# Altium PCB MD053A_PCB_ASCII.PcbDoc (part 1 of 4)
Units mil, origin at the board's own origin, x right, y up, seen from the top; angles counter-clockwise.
Board outline 3650 x 5180 mil, 4 copper layers (Top Layer, GND Layer, Power Layer, Bottom Layer), stack 58.4 mil thick; 251 components, 138 nets, 532 pads, 1017 vias.
Unrouted connection lines stored in the file: 42.
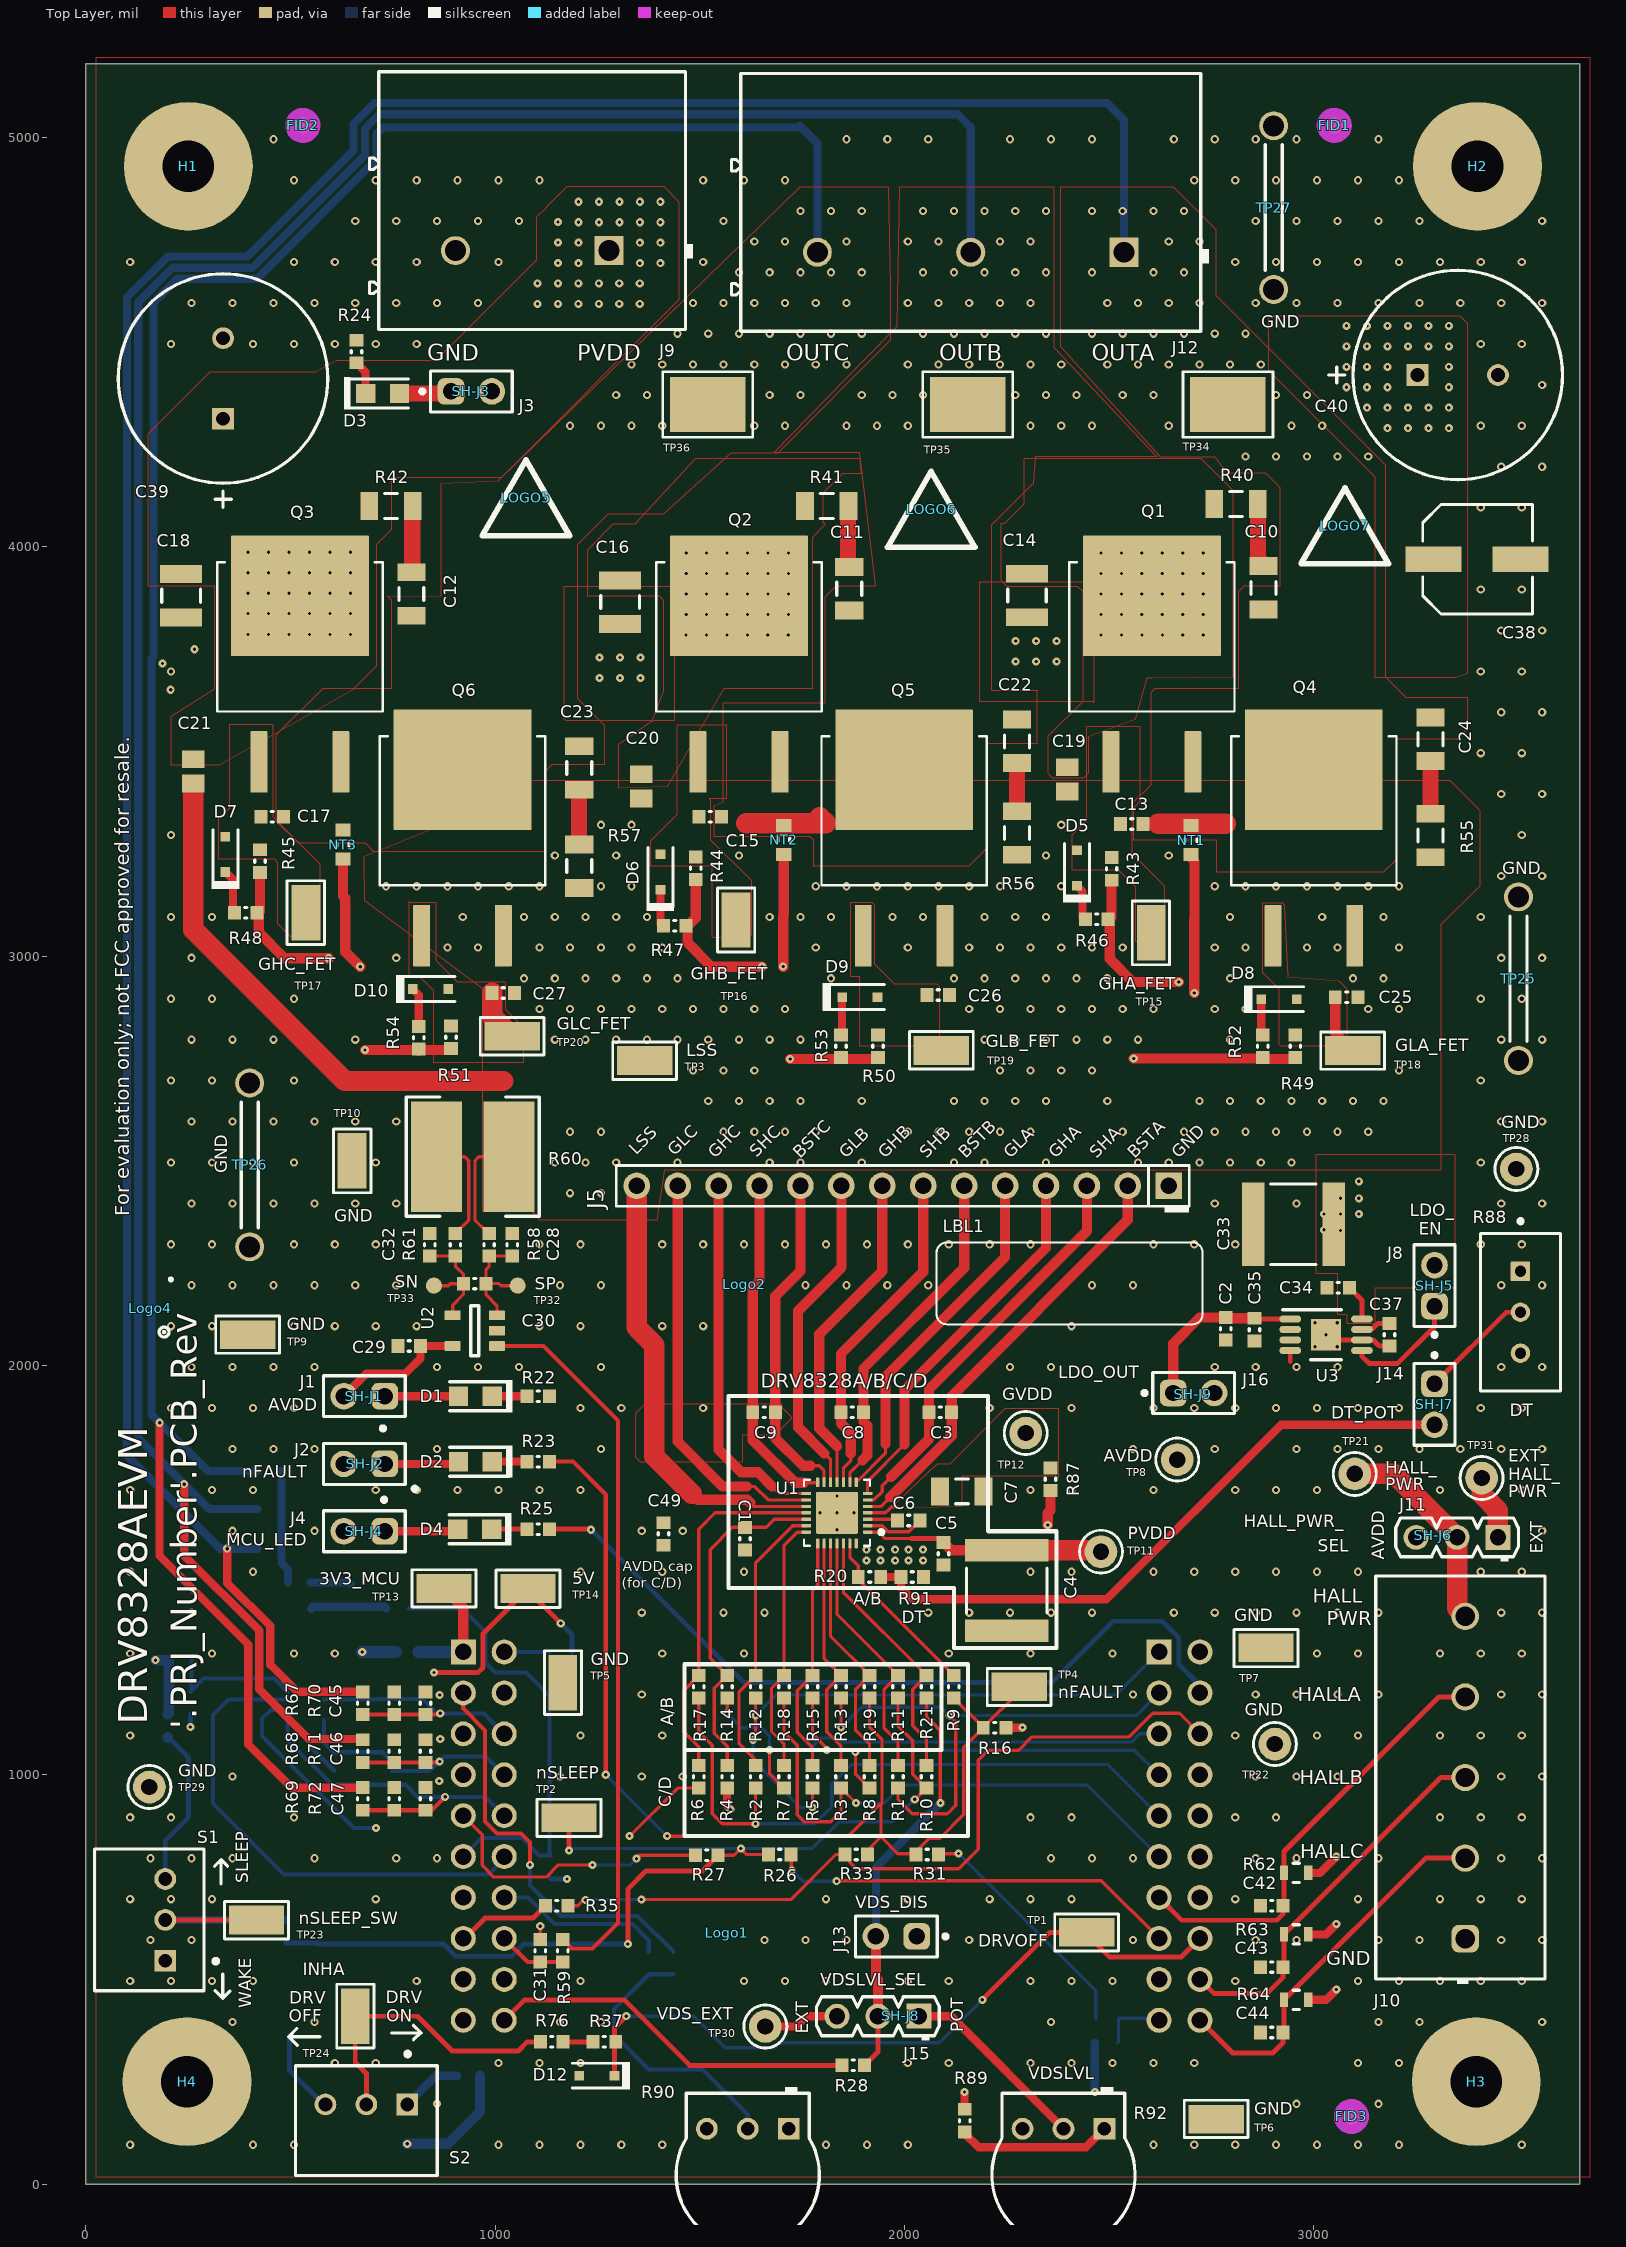
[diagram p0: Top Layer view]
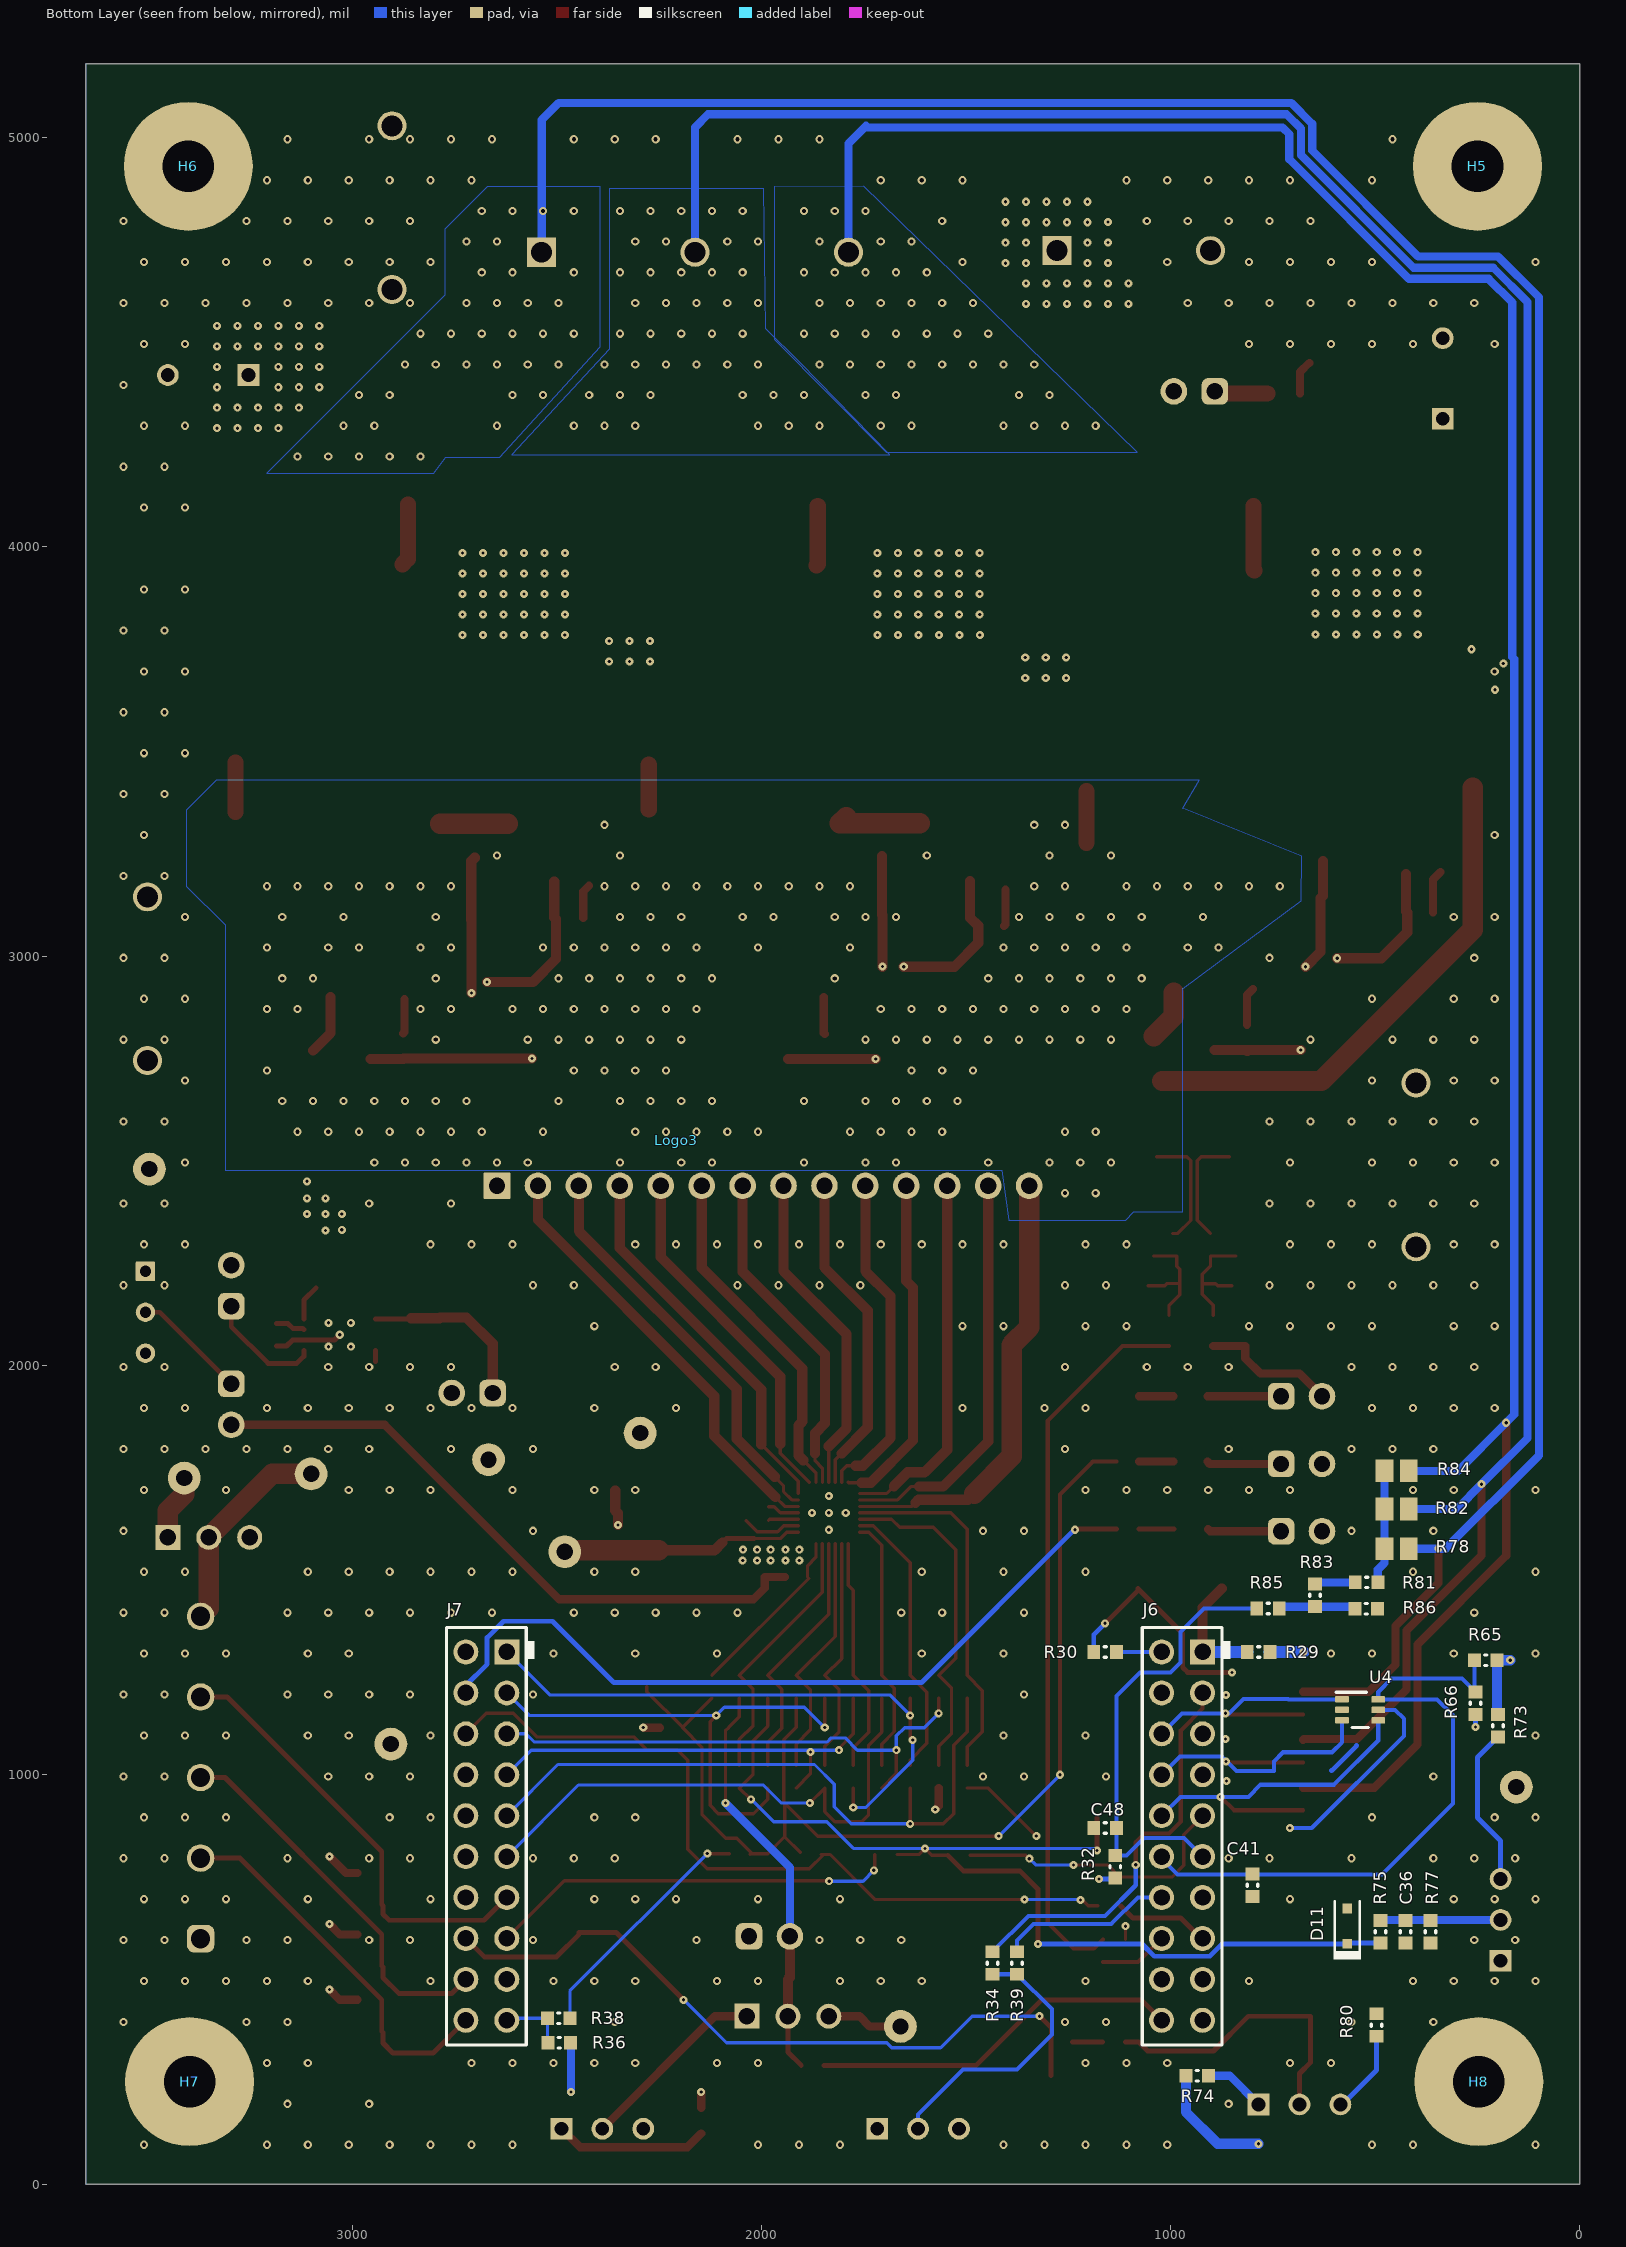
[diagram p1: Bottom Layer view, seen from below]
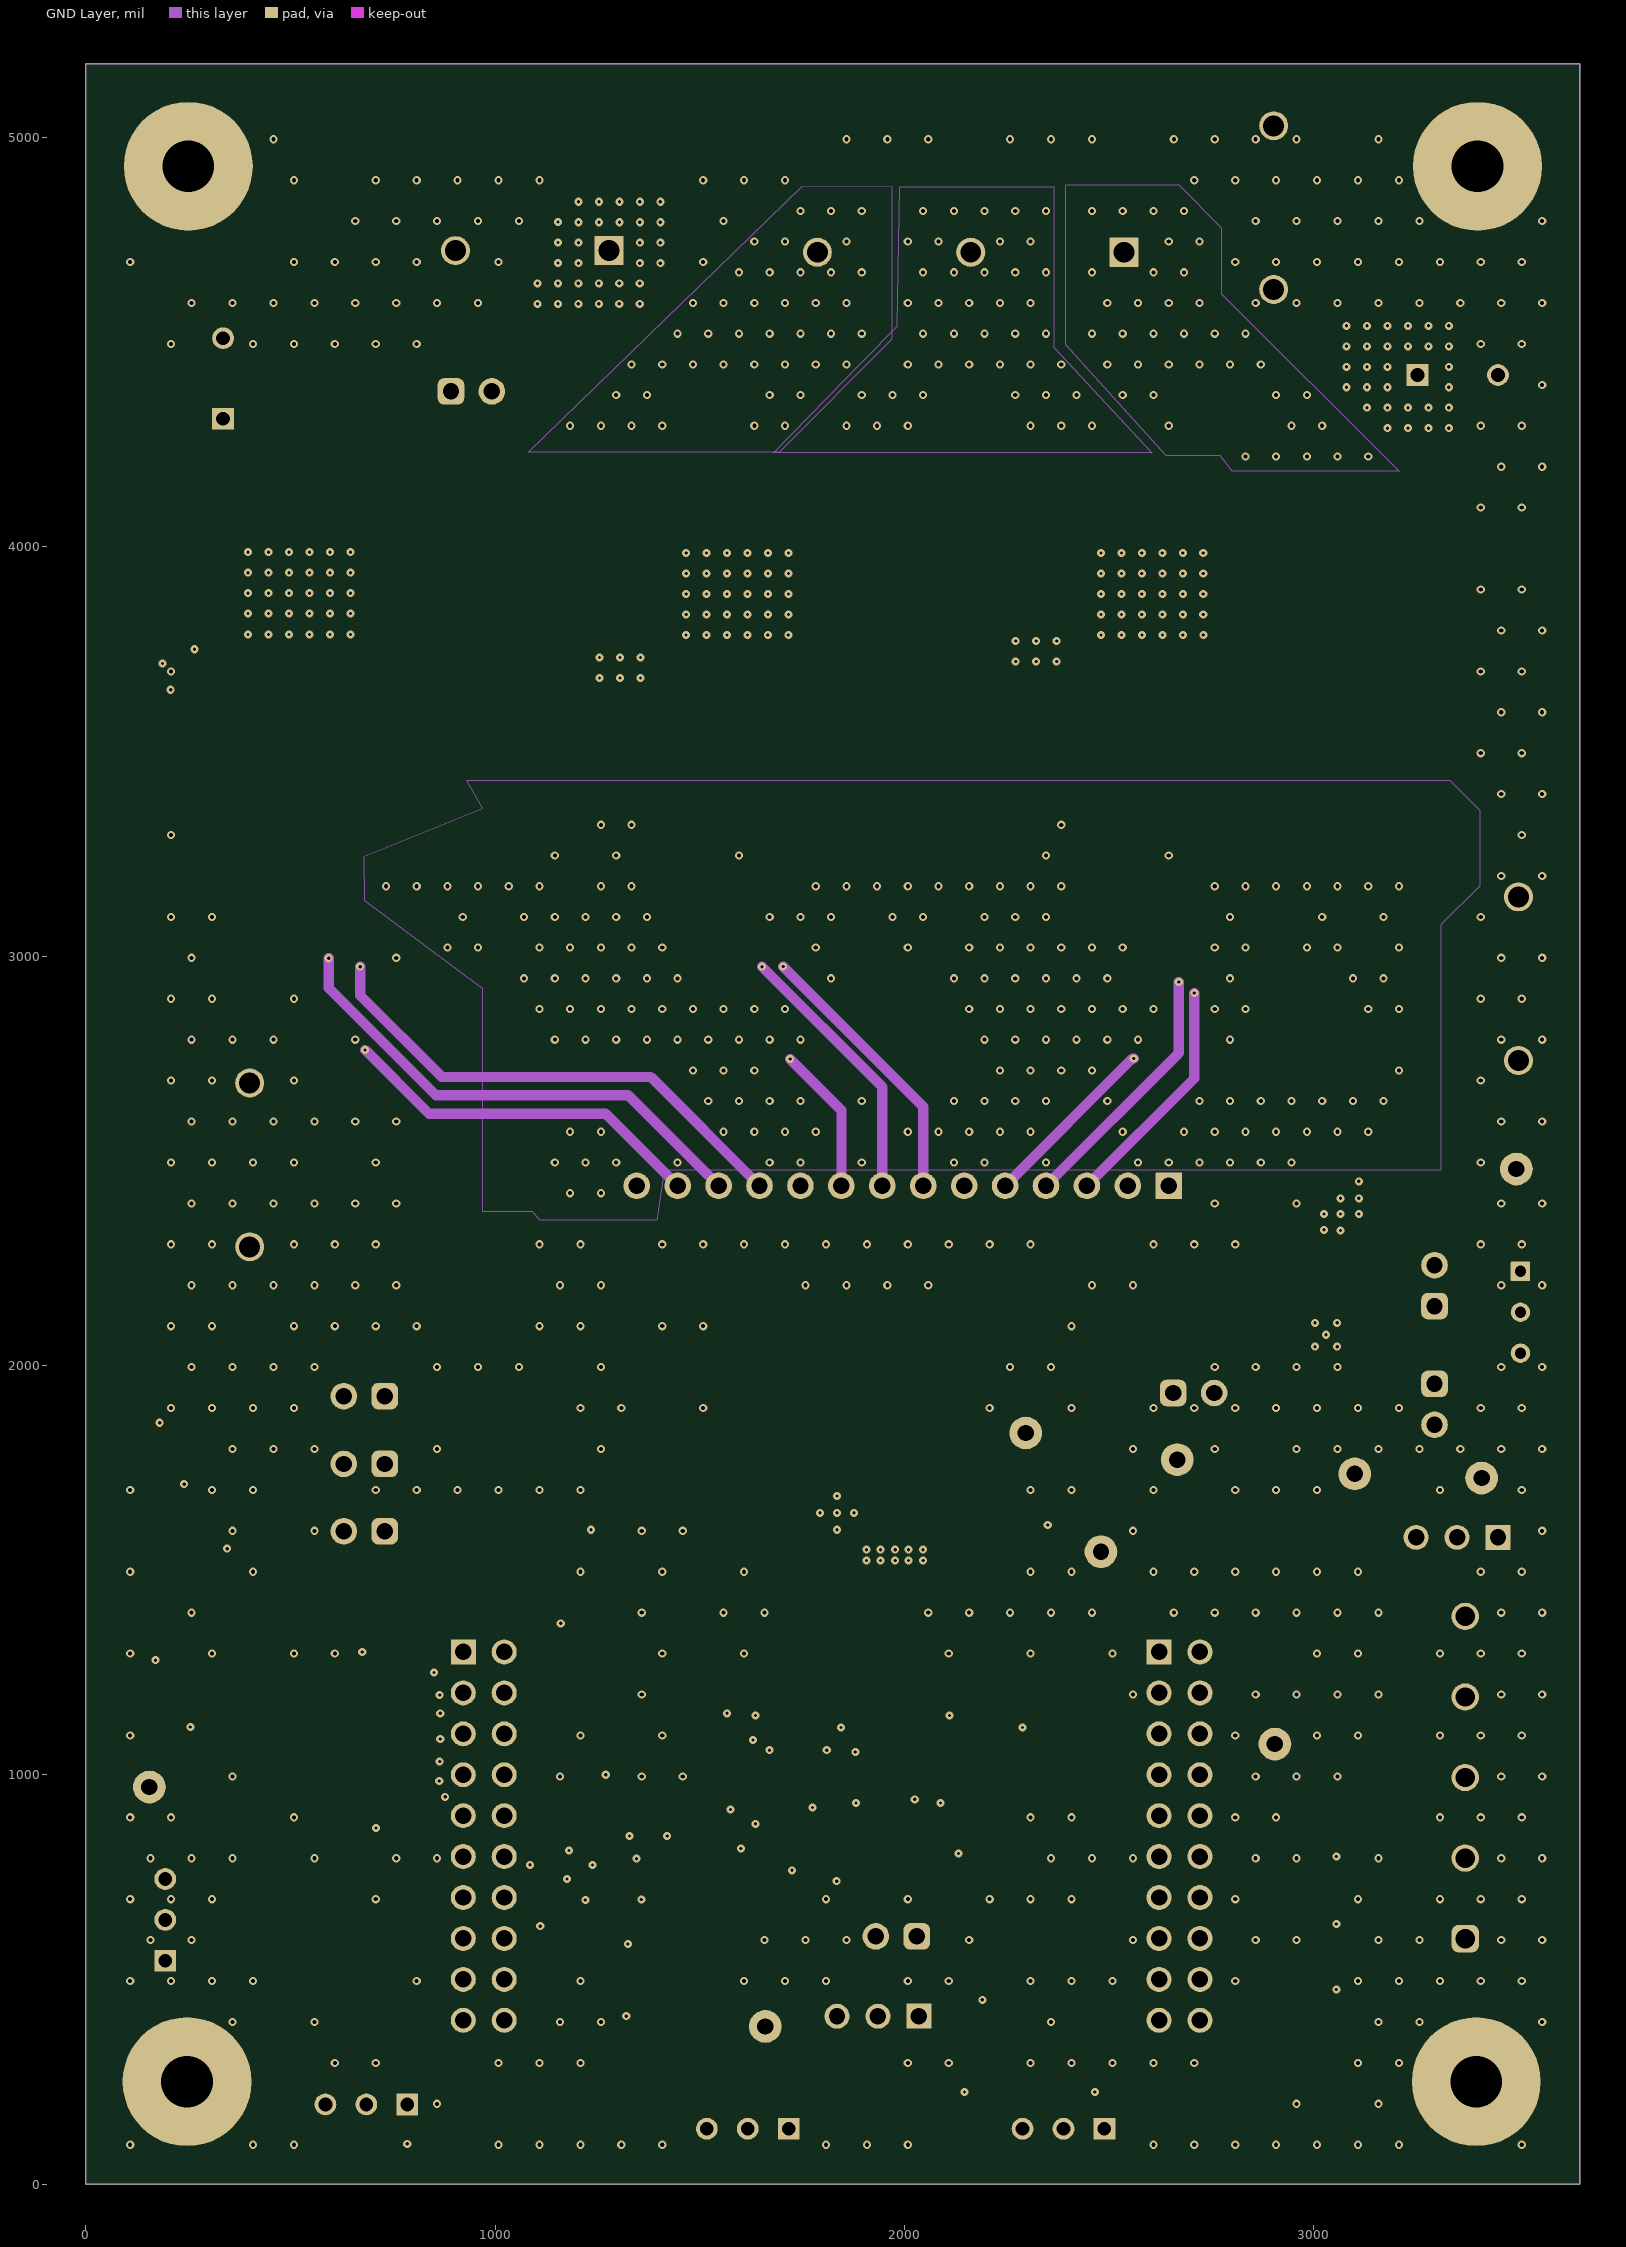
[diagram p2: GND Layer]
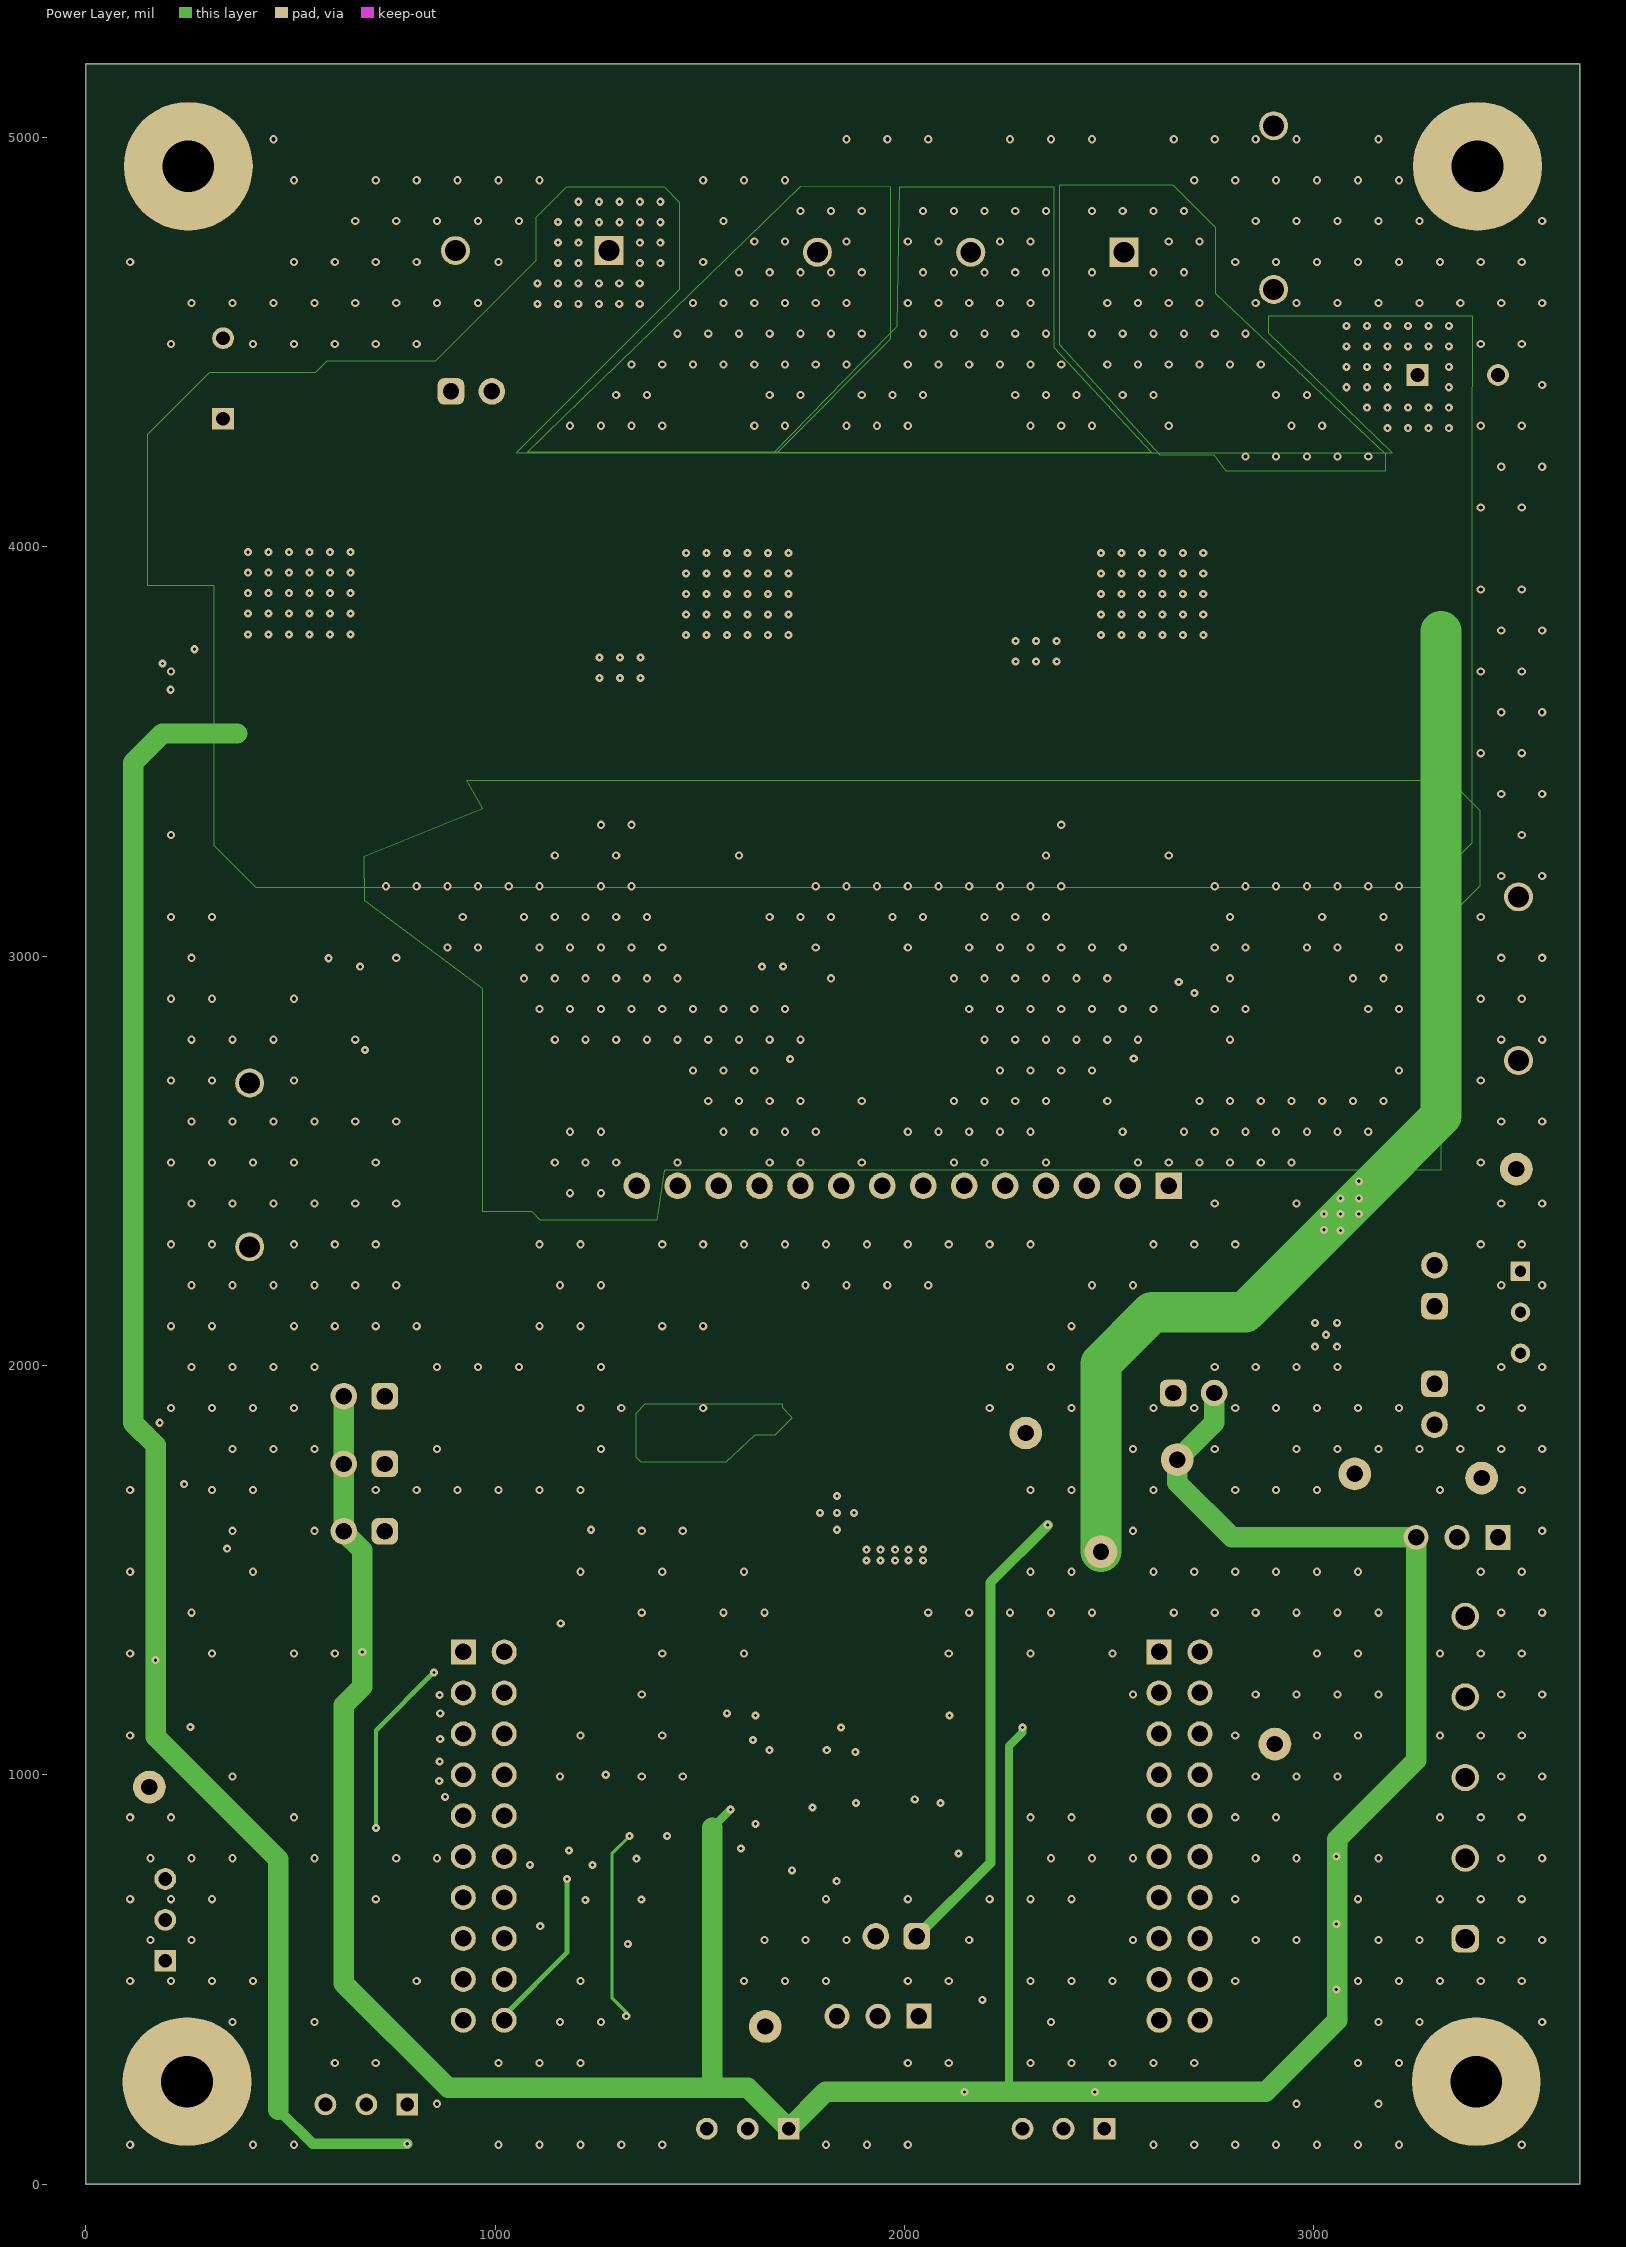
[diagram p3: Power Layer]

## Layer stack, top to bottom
Top Solder: solder mask 0.4, Solder Resist, Dk 3.5
Top Layer: signal copper 2.8
Dielectric 2: core 10, FR-4, Dk 4.8
GND Layer: signal copper 1.4
Dielectric 1: prepreg 30, FR-4, Dk 4.2
Power Layer: signal copper 1.4
Dielectric 3: core 10, FR-4, Dk 4.8
Bottom Layer: signal copper 2.8
Solder Side: solder mask 0.4, Solder Resist, Dk 3.5

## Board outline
0,0 3650,0 3650,5180 0,5180

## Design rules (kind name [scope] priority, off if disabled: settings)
AcuteAngle [All] p0: scope1count=1 scope1_0_kind=Board scope1_0_value=Board scope2count=1 scope2_0_kind=Board scope2_0_value=Board commentlength=0 minimum=4.50000000000000E+0001
AcuteAngle [All] p1: minimum=4.50000000000000E+0001 checktracksonly=FALSE
AssemblyTestPointUsage [All] p0: scope1count=1 scope1_0_kind=Board scope1_0_value=Board scope2count=1 scope2_0_kind=Board scope2_0_value=Board commentlength=0
AssemblyTestPointUsage [All] p1: valid=2
AssemblyTestpoint [All] p0: scope1count=1 scope1_0_kind=Board scope1_0_value=Board scope2count=1 scope2_0_kind=Board scope2_0_value=Board commentlength=0
BoardOutlineClearance [All] p0 off: scope1count=1 scope1_0_kind=Board scope1_0_value=Board scope2count=1 scope2_0_kind=Board scope2_0_value=Board commentlength=172 gap=75 // Protel DXP Scope 1 Expression Was: OnCopper and Not InComponentClass('Logo') and not InComponentClass('FiducialMark') and not InRegion(1000,500,4000,800) and not InPoly
BoardOutlineClearance BoardOutlineClearance_Poly [All] p0 off: scope1count=1 scope1_0_kind=Board scope1_0_value=Board scope2count=1 scope2_0_kind=Board scope2_0_value=Board commentlength=58 gap=25 // Protel DXP Scope 1 Expression Was: OnCopper and IsPoly
BoardOutlineClearance BoardOutlineClearance_MountingHoles [All] p0 off: scope1count=1 scope1_0_kind=Board scope1_0_value=Board scope2count=1 scope2_0_kind=Board scope2_0_value=Board commentlength=86 gap=39.37 // Protel DXP Scope 1 Expression Was: OnCopper and InComponentClass('Mounting Holes')
BoardOutlineClearance BoardOutlineClearance_MountingHoles [OnCopper and InComponentClass('Mounting Holes')] p1: gap=39.37 ignorepadtopadclearanceinfootprint=FALSE
BoardOutlineClearance BoardOutlineClearance_Poly [OnCopper and IsPoly] p2: gap=25 ignorepadtopadclearanceinfootprint=FALSE
BoardOutlineClearance [OnCopper and Not InComponentClass('Logo') and not InComponentClass('FiducialMark') and not InRegion(1000,500,4000,800) and not InPoly] p3: gap=75 ignorepadtopadclearanceinfootprint=FALSE
Clearance [All] p0: scope1count=1 scope1_0_kind=Board scope1_0_value=Board scope2count=1 scope2_0_kind=Board scope2_0_value=Board commentlength=0 gap=7
Clearance Clearance_FiducialMark [All] p0 off: scope1count=1 scope1_0_kind=Board scope1_0_value=Board scope2count=1 scope2_0_kind=Board scope2_0_value=Board commentlength=81 gap=0 // Protel DXP Scope 2 Expression Was: IsPad and InComponentClass('FiducialMark')
Clearance Clearance_Poly [All] p0 off: scope1count=1 scope1_0_kind=Board scope1_0_value=Board scope2count=1 scope2_0_kind=Board scope2_0_value=Board commentlength=48 gap=10 // Protel DXP Scope 1 Expression Was: InPolygon
Clearance Clearance_Keepouts [All] p0 off: scope1count=1 scope1_0_kind=Board scope1_0_value=Board scope2count=1 scope2_0_kind=Board scope2_0_value=Board commentlength=99 gap=0 // Protel DXP Scope 2 Expression Was: ((IsTrack Or IsArc) And Not InPoly) And IsFree and IsKeepOut
Clearance Clearance_Keepouts [((IsTrack Or IsArc) And Not InPoly) And IsFree and IsKeepOut vs ((IsTrack Or IsArc) And Not InPoly) And IsFree and IsKeepOut] p1: gap=0 ignorepadtopadclearanceinfootprint=FALSE
Clearance Clearance_Poly [InPolygon] p2: gap=10 ignorepadtopadclearanceinfootprint=TRUE
Clearance Clearance_FiducialMark [IsKeepOut and InComponentClass('FiducialMark') vs IsPad and InComponentClass('FiducialMark')] p3: gap=0 ignorepadtopadclearanceinfootprint=FALSE
Clearance [All] p4: gap=7 ignorepadtopadclearanceinfootprint=TRUE
ComponentClearance [All] p0: scope1count=1 scope1_0_kind=Board scope1_0_value=Board scope2count=1 scope2_0_kind=Board scope2_0_value=Board commentlength=0 gap=30 collisioncheckmode=3
ComponentClearance ComponentClearance_THtoTH [All] p0 off: scope1count=1 scope1_0_kind=Board scope1_0_value=Board scope2count=1 scope2_0_kind=Board scope2_0_value=Board commentlength=54 gap=30 collisioncheckmode=3 // Protel DXP Scope 2 Expression Was: IsThruComponent
ComponentClearance ComponentClearance_THtoSMT [All] p0 off: scope1count=1 scope1_0_kind=Board scope1_0_value=Board scope2count=1 scope2_0_kind=Board scope2_0_value=Board commentlength=53 gap=40 collisioncheckmode=3 // Protel DXP Scope 2 Expression Was: IsSMTComponent
ComponentClearance ComponentClearance_SmallPassives [All] p0 off: scope1count=1 scope1_0_kind=Board scope1_0_value=Board scope2count=1 scope2_0_kind=Board scope2_0_value=Board commentlength=508 gap=14.96 collisioncheckmode=3 // Protel DXP Scope 2 Expression Was: HasFootprint('0201*') or HasFootprint('0402*') or HasFootprint('0508') or HasFootprint('0603*') or HasFootprint('0612') or HasFootprint('0805*') or HasFootprint('0815*') or HasFootprint('0830*') or HasFootprint('1206*') or HasFootprint('1210*') or HasFootprint('1808*') or HasFootprint('1812*') or HasFootprint('1825*') or HasFootprint('2010*') or HasFootprint('2220*') or HasFootprint('2225*') or HasFootprint('2512*') or HasFootprint('2728*') or HasFootprint('3518*')
ComponentClearance ComponentClearance_MountingHoles [All] p0: scope1count=1 scope1_0_kind=ComponentClass scope1_0_value="Mounting Holes" scope2count=1 scope2_0_kind=Board scope2_0_value=Board commentlength=0 gap=10 collisioncheckmode=3
ComponentClearance ComponentClearance_ScrewToNut [All] p0 off: scope1count=1 scope1_0_kind=Board scope1_0_value=Board scope2count=1 scope2_0_kind=Board scope2_0_value=Board commentlength=71 gap=5 collisioncheckmode=3 // Protel DXP Scope 2 Expression Was: (HasFootprint('Keystone_1902C'))
ComponentClearance ComponentClearance_Logo [All] p0: scope1count=1 scope1_0_kind=ComponentClass scope1_0_value=Logo scope2count=1 scope2_0_kind=Board scope2_0_value=Board commentlength=0 gap=50 collisioncheckmode=3
ComponentClearance ComponentClearance_Shunt [All] p0: scope1count=1 scope1_0_kind=ComponentClass scope1_0_value=Header scope2count=1 scope2_0_kind=ComponentClass scope2_0_value=Shunt commentlength=0 gap=0 collisioncheckmode=3
ComponentClearance ComponentClearance_MountingHoles_FiducialMarks [All] p0: scope1count=1 scope1_0_kind=ComponentClass scope1_0_value="Mounting Holes" scope2count=1 scope2_0_kind=ComponentClass scope2_0_value=FiducialMark commentlength=0 gap=50 collisioncheckmode=3
ComponentClearance ComponentClearance_MountingHoles_FiducialMarks [InComponentClass('Mounting Holes') vs InComponentClass('FiducialMark')] p1: gap=50 collisioncheckmode=3 verticalgap=10 showdistances=FALSE
ComponentClearance ComponentClearance_Shunt [InComponentClass('Header') vs InComponentClass('Shunt')] p2: gap=0 collisioncheckmode=3 verticalgap=0 showdistances=FALSE
ComponentClearance ComponentClearance_Logo [InComponentClass('Logo')] p3: gap=50 collisioncheckmode=3 verticalgap=10 showdistances=FALSE
ComponentClearance ComponentClearance_ScrewToNut [(HasFootprint('NY PMS 440 0025 PH')) vs (HasFootprint('Keystone_1902C'))] p4: gap=5 collisioncheckmode=3 verticalgap=10 showdistances=FALSE
ComponentClearance ComponentClearance_MountingHoles [InComponentClass('Mounting Holes')] p5: gap=10 collisioncheckmode=3 verticalgap=100000 showdistances=FALSE
ComponentClearance ComponentClearance_SmallPassives [HasFootprint('0201*') or HasFootprint('0402*') or HasFootprint('0508') or HasFootprint('0603*') or HasFootprint('0612') or HasFootprint('0805*') or HasFootprint('0815*') or HasFootprint('0830*') or HasFootprint('1206*') or HasFootprint('1210*') or HasFootprint('1808*') or HasFootprint('1812*') or HasFootprint('1825*') or HasFootprint('2010*') or HasFootprint('2220*') or HasFootprint('2225*') or HasFootprint('2512*') or HasFootprint('2728*') or HasFootprint('3518*') vs HasFootprint('0201*') or HasFootprint('0402*') or HasFootprint('0508') or HasFootprint('0603*') or HasFootprint('0612') or HasFootprint('0805*') or HasFootprint('0815*') or HasFootprint('0830*') or HasFootprint('1206*') or HasFootprint('1210*') or HasFootprint('1808*') or HasFootprint('1812*') or HasFootprint('1825*') or HasFootprint('2010*') or HasFootprint('2220*') or HasFootprint('2225*') or HasFootprint('2512*') or HasFootprint('2728*') or HasFootprint('3518*')] p6: gap=14.96 collisioncheckmode=3 verticalgap=10 showdistances=FALSE
ComponentClearance ComponentClearance_THtoSMT [IsThruComponent vs IsSMTComponent] p7: gap=40 collisioncheckmode=3 verticalgap=30 showdistances=FALSE
ComponentClearance ComponentClearance_THtoTH [IsThruComponent vs IsThruComponent] p8: gap=30 collisioncheckmode=3 verticalgap=30 showdistances=FALSE
ComponentClearance [All] p9: gap=30 collisioncheckmode=3 verticalgap=10 showdistances=FALSE
DiffPairsRouting [All] p0: scope1count=1 scope1_0_kind=Board scope1_0_value=Board scope2count=1 scope2_0_kind=Board scope2_0_value=Board commentlength=0
DiffPairsRouting [All] p1: maxlimit=100 minlimit=10 mostfreqgap=10 toplayer_minwidth=15 toplayer_maxwidth=15 toplayer_prefwidth=15 midlayer1_minwidth=15 midlayer1_maxwidth=15 midlayer1_prefwidth=15 midlayer2_minwidth=15 midlayer2_maxwidth=15 midlayer2_prefwidth=15 bottomlayer_minwidth=15 bottomlayer_maxwidth=15 bottomlayer_prefwidth=15 maxuncoupledlength=1000
FabricationTestPointUsage TestPointUsage [All] p0: scope1count=1 scope1_0_kind=Board scope1_0_value=Board scope2count=1 scope2_0_kind=Board scope2_0_value=Board commentlength=0 valid=2 allowmultiple=FALSE
FabricationTestPointUsage TestPointUsage [All] p1: valid=2 allowmultiple=FALSE
FabricationTestpoint Testpoint [All] p0: scope1count=1 scope1_0_kind=Board scope1_0_value=Board scope2count=1 scope2_0_kind=Board scope2_0_value=Board commentlength=0 side=3 testpointundercomponent=TRUE minsize=40 maxsize=100 preferedsize=60 minholesize=0 maxholesize=40 preferedholesize=32 testpointgrid=1
FabricationTestpoint Testpoint [All] p1: side=3 testpointundercomponent=TRUE minsize=40 maxsize=100 preferedsize=60 minholesize=0 maxholesize=40 preferedholesize=32 testpointgrid=1 allowsidetop=TRUE allowsidebottom=TRUE usegrid=TRUE gridtolerance=0.01
FanoutControl Fanout_Small [All] p0 off: scope1count=1 scope1_0_kind=Board scope1_0_value=Board scope2count=1 scope2_0_kind=Board scope2_0_value=Board commentlength=84 // Protel DXP Scope 1 Expression Was: (CompPinCount < 5)   Fanout_Small (Default Rule)
FanoutControl Fanout_Default [All] p0: scope1count=1 scope1_0_kind=Board scope1_0_value=Board scope2count=1 scope2_0_kind=Board scope2_0_value=Board commentlength=30 // Fanout_Default (Default Rule)
FanoutControl Fanout_SOIC [All] p0 off: scope1count=1 scope1_0_kind=Board scope1_0_value=Board scope2count=1 scope2_0_kind=Board scope2_0_value=Board commentlength=71 // Protel DXP Scope 1 Expression Was: IsSOIC   Fanout_SOIC (Default Rule)
FanoutControl Fanout_BGA [All] p0 off: scope1count=1 scope1_0_kind=Board scope1_0_value=Board scope2count=1 scope2_0_kind=Board scope2_0_value=Board commentlength=69 // Protel DXP Scope 1 Expression Was: IsBGA   Fanout_BGA (Default Rule)
FanoutControl Fanout_LCC [All] p0 off: scope1count=1 scope1_0_kind=Board scope1_0_value=Board scope2count=1 scope2_0_kind=Board scope2_0_value=Board commentlength=69 // Protel DXP Scope 1 Expression Was: IsLCC   Fanout_LCC (Default Rule)
FanoutControl Fanout_LCC [IsLCC] p1: bgadir=Out bgaviamode=Centered fanoutstyle=Auto fanoutdirection=Alternating viagrid=1 // Fanout_LCC (Default Rule)
FanoutControl Fanout_BGA [IsBGA] p2: bgadir=Out bgaviamode=Centered fanoutstyle=Auto fanoutdirection=Alternating viagrid=1 // Fanout_BGA (Default Rule)
FanoutControl Fanout_Default [All] p4: bgadir=Out bgaviamode=Centered fanoutstyle=Auto fanoutdirection=Alternating viagrid=1 // Fanout_Default (Default Rule)
FanoutControl Fanout_Small [(CompPinCount < 5)] p5: bgadir=Out bgaviamode=Centered fanoutstyle=Auto fanoutdirection=OutThenIn viagrid=1 // Fanout_Small (Default Rule)
Height [All] p0 off: scope1count=1 scope1_0_kind=Board scope1_0_value=Board scope2count=1 scope2_0_kind=Board scope2_0_value=Board commentlength=0
Height [All] p1 off: minheight=0 maxheight=1000 prefheight=500
HoleSize [All] p0: scope1count=1 scope1_0_kind=Board scope1_0_value=Board scope2count=1 scope2_0_kind=Board scope2_0_value=Board commentlength=0 absolutevalues=TRUE maxlimit=251 minlimit=7.87 maxpercent=80.000 minpercent=20.000
HoleSize [All] p1: absolutevalues=TRUE maxlimit=251 minlimit=7.87 maxpercent=80.000 minpercent=20.000
HoleToHoleClearance [All] p0: scope1count=1 scope1_0_kind=Board scope1_0_value=Board scope2count=1 scope2_0_kind=Board scope2_0_value=Board commentlength=0
LayerPairs [All] p0: scope1count=1 scope1_0_kind=Board scope1_0_value=Board scope2count=1 scope2_0_kind=Board scope2_0_value=Board commentlength=0 enforce=TRUE
MinimumAnnularRing [All] p0: scope1count=1 scope1_0_kind=Board scope1_0_value=Board scope2count=1 scope2_0_kind=Board scope2_0_value=Board commentlength=0 minimumring=5
MinimumAnnularRing MinimumAnnularRing_ThermalPadVias [All] p0 off: scope1count=1 scope1_0_kind=Board scope1_0_value=Board scope2count=1 scope2_0_kind=Board scope2_0_value=Board commentlength=63 minimumring=5.91 // Protel DXP Scope 1 Expression Was: IsVia and InAnyComponent
MinimumAnnularRing MinimumAnnularRing_ThermalPadVias [IsVia and InAnyComponent] p1: minimumring=5.91
MinimumAnnularRing [All] p2: minimumring=5
MinimumSolderMaskSliver [All] p0: scope1count=1 scope1_0_kind=Board scope1_0_value=Board scope2count=1 scope2_0_kind=Board scope2_0_value=Board commentlength=0
MinimumSolderMaskSliver MinimumSolderMaskSliver_Logo [All] p0: scope1count=1 scope1_0_kind=ComponentClass scope1_0_value=Logo scope2count=1 scope2_0_kind=ComponentClass scope2_0_value=Logo commentlength=0
MinimumSolderMaskSliver MinimumSolderMaskSliver_Logo [InComponentClass('Logo') vs InComponentClass('Logo')] p1: minsoldermaskwidth=0.7
MinimumSolderMaskSliver [All] p2: minsoldermaskwidth=1
NetAntennae [All] p0: scope1count=1 scope1_0_kind=Board scope1_0_value=Board scope2count=1 scope2_0_kind=Board scope2_0_value=Board commentlength=0
PasteMaskExpansion [All] p0: scope1count=1 scope1_0_kind=Board scope1_0_value=Board scope2count=1 scope2_0_kind=Board scope2_0_value=Board commentlength=0 expansion=0
PlaneClearance [All] p0: scope1count=1 scope1_0_kind=Board scope1_0_value=Board scope2count=1 scope2_0_kind=Board scope2_0_value=Board commentlength=0 clearance=20
PlaneConnect [All] p0: scope1count=1 scope1_0_kind=Board scope1_0_value=Board scope2count=1 scope2_0_kind=Board scope2_0_value=Board commentlength=0 planeconnectstyle=Direct reliefexpansion=10 reliefentries=4 reliefconductorwidth=10 reliefairgap=10
PlaneConnect [All] p1: planeconnectstyle=Direct reliefexpansion=10 reliefentries=4 reliefconductorwidth=10 reliefairgap=10
PolygonConnect PolygonConnect_51 [All] p0: scope1count=1 scope1_0_kind=Board scope1_0_value=Board scope2count=1 scope2_0_kind=Board scope2_0_value=Board commentlength=0 connectstyle=Direct reliefconductorwidth=10 reliefentries=4 polygonreliefangle="90 Angle"
PolygonConnect PolygonConnect_50 [All] p0 off: scope1count=1 scope1_0_kind=Board scope1_0_value=Board scope2count=1 scope2_0_kind=Board scope2_0_value=Board commentlength=76 connectstyle=Direct reliefconductorwidth=10 reliefentries=4 polygonreliefangle="90 Angle" // Protel DXP Scope 2 Expression Was: IsNamedPolygon('TOP_LAYER_PVDD_P078')
PolygonConnect PolygonConnect_49 [All] p0 off: scope1count=1 scope1_0_kind=Board scope1_0_value=Board scope2count=1 scope2_0_kind=Board scope2_0_value=Board commentlength=76 connectstyle=Direct reliefconductorwidth=10 reliefentries=4 polygonreliefangle="90 Angle" // Protel DXP Scope 2 Expression Was: IsNamedPolygon('TOP_LAYER_PVDD_P078')
PolygonConnect PolygonConnect_48 [All] p0 off: scope1count=1 scope1_0_kind=Board scope1_0_value=Board scope2count=1 scope2_0_kind=Board scope2_0_value=Board commentlength=76 connectstyle=Direct reliefconductorwidth=10 reliefentries=4 polygonreliefangle="90 Angle" // Protel DXP Scope 2 Expression Was: IsNamedPolygon('TOP_LAYER_PVDD_P078')
PolygonConnect PolygonConnect_47 [All] p0 off: scope1count=1 scope1_0_kind=Board scope1_0_value=Board scope2count=1 scope2_0_kind=Board scope2_0_value=Board commentlength=76 connectstyle=Direct reliefconductorwidth=10 reliefentries=4 polygonreliefangle="90 Angle" // Protel DXP Scope 2 Expression Was: IsNamedPolygon('TOP_LAYER_PVDD_P008')
PolygonConnect PolygonConnect_46 [All] p0 off: scope1count=1 scope1_0_kind=Board scope1_0_value=Board scope2count=1 scope2_0_kind=Board scope2_0_value=Board commentlength=78 connectstyle=Direct reliefconductorwidth=10 reliefentries=4 polygonreliefangle="90 Angle" // Protel DXP Scope 2 Expression Was: IsNamedPolygon('BOTTOM_LAYER_GND_P080')
PolygonConnect PolygonConnect_45 [All] p0 off: scope1count=1 scope1_0_kind=Board scope1_0_value=Board scope2count=1 scope2_0_kind=Board scope2_0_value=Board commentlength=79 connectstyle=Direct reliefconductorwidth=10 reliefentries=4 polygonreliefangle="90 Angle" // Protel DXP Scope 2 Expression Was: IsNamedPolygon('BOTTOM_LAYER_OUTA_P076')
PolygonConnect PolygonConnect_44 [All] p0 off: scope1count=1 scope1_0_kind=Board scope1_0_value=Board scope2count=1 scope2_0_kind=Board scope2_0_value=Board commentlength=79 connectstyle=Direct reliefconductorwidth=10 reliefentries=4 polygonreliefangle="90 Angle" // Protel DXP Scope 2 Expression Was: IsNamedPolygon('BOTTOM_LAYER_OUTB_P074')
PolygonConnect PolygonConnect_43 [All] p0 off: scope1count=1 scope1_0_kind=Board scope1_0_value=Board scope2count=1 scope2_0_kind=Board scope2_0_value=Board commentlength=79 connectstyle=Direct reliefconductorwidth=10 reliefentries=4 polygonreliefangle="90 Angle" // Protel DXP Scope 2 Expression Was: IsNamedPolygon('BOTTOM_LAYER_OUTC_P072')
PolygonConnect PolygonConnect_42 [All] p0 off: scope1count=1 scope1_0_kind=Board scope1_0_value=Board scope2count=1 scope2_0_kind=Board scope2_0_value=Board commentlength=80 connectstyle=Direct reliefconductorwidth=10 reliefentries=4 polygonreliefangle="90 Angle" // Protel DXP Scope 2 Expression Was: IsNamedPolygon('BOTTOM_LAYER_NONET_P070')
PolygonConnect PolygonConnect_41 [All] p0 off: scope1count=1 scope1_0_kind=Board scope1_0_value=Board scope2count=1 scope2_0_kind=Board scope2_0_value=Board commentlength=77 connectstyle=Direct reliefconductorwidth=10 reliefentries=4 polygonreliefangle="90 Angle" // Protel DXP Scope 2 Expression Was: IsNamedPolygon('POWER_LAYER_GND_P078')
PolygonConnect PolygonConnect_40 [All] p0 off: scope1count=1 scope1_0_kind=Board scope1_0_value=Board scope2count=1 scope2_0_kind=Board scope2_0_value=Board commentlength=75 connectstyle=Direct reliefconductorwidth=10 reliefentries=4 polygonreliefangle="90 Angle" // Protel DXP Scope 2 Expression Was: IsNamedPolygon('GND_LAYER_GND_P074')
PolygonConnect PolygonConnect_39 [All] p0 off: scope1count=1 scope1_0_kind=Board scope1_0_value=Board scope2count=1 scope2_0_kind=Board scope2_0_value=Board commentlength=75 connectstyle=Direct reliefconductorwidth=10 reliefentries=4 polygonreliefangle="90 Angle" // Protel DXP Scope 2 Expression Was: IsNamedPolygon('TOP_LAYER_GND_P070')
PolygonConnect PolygonConnect_38 [All] p0 off: scope1count=1 scope1_0_kind=Board scope1_0_value=Board scope2count=1 scope2_0_kind=Board scope2_0_value=Board commentlength=73 connectstyle=Direct reliefconductorwidth=10 reliefentries=4 polygonreliefangle="90 Angle" // Protel DXP Scope 2 Expression Was: IsNamedPolygon('BOTTOM_LAYER_GND')
PolygonConnect PolygonConnect_37 [All] p0 off: scope1count=1 scope1_0_kind=Board scope1_0_value=Board scope2count=1 scope2_0_kind=Board scope2_0_value=Board commentlength=73 connectstyle=Direct reliefconductorwidth=10 reliefentries=4 polygonreliefangle="90 Angle" // Protel DXP Scope 2 Expression Was: IsNamedPolygon('BOTTOM_LAYER_GND')
PolygonConnect PolygonConnect_36 [All] p0 off: scope1count=1 scope1_0_kind=Board scope1_0_value=Board scope2count=1 scope2_0_kind=Board scope2_0_value=Board commentlength=76 connectstyle=Direct reliefconductorwidth=10 reliefentries=4 polygonreliefangle="90 Angle" // Protel DXP Scope 2 Expression Was: IsNamedPolygon('GND_LAYER_OUTA_P062')
PolygonConnect PolygonConnect_35 [All] p0 off: scope1count=1 scope1_0_kind=Board scope1_0_value=Board scope2count=1 scope2_0_kind=Board scope2_0_value=Board commentlength=76 connectstyle=Direct reliefconductorwidth=10 reliefentries=4 polygonreliefangle="90 Angle" // Protel DXP Scope 2 Expression Was: IsNamedPolygon('GND_LAYER_OUTB_P060')
PolygonConnect PolygonConnect_34 [All] p0 off: scope1count=1 scope1_0_kind=Board scope1_0_value=Board scope2count=1 scope2_0_kind=Board scope2_0_value=Board commentlength=76 connectstyle=Direct reliefconductorwidth=10 reliefentries=4 polygonreliefangle="90 Angle" // Protel DXP Scope 2 Expression Was: IsNamedPolygon('GND_LAYER_OUTC_P058')
PolygonConnect PolygonConnect_33 [All] p0 off: scope1count=1 scope1_0_kind=Board scope1_0_value=Board scope2count=1 scope2_0_kind=Board scope2_0_value=Board commentlength=78 connectstyle=Direct reliefconductorwidth=10 reliefentries=4 polygonreliefangle="90 Angle" // Protel DXP Scope 2 Expression Was: IsNamedPolygon('POWER_LAYER_PVDD_P056')
PolygonConnect PolygonConnect_32 [All] p0 off: scope1count=1 scope1_0_kind=Board scope1_0_value=Board scope2count=1 scope2_0_kind=Board scope2_0_value=Board commentlength=78 connectstyle=Direct reliefconductorwidth=10 reliefentries=4 polygonreliefangle="90 Angle" // Protel DXP Scope 2 Expression Was: IsNamedPolygon('POWER_LAYER_PVDD_P056')
PolygonConnect PolygonConnect_31 [All] p0 off: scope1count=1 scope1_0_kind=Board scope1_0_value=Board scope2count=1 scope2_0_kind=Board scope2_0_value=Board commentlength=78 connectstyle=Direct reliefconductorwidth=10 reliefentries=4 polygonreliefangle="90 Angle" // Protel DXP Scope 2 Expression Was: IsNamedPolygon('POWER_LAYER_OUTA_P052')
PolygonConnect PolygonConnect_30 [All] p0 off: scope1count=1 scope1_0_kind=Board scope1_0_value=Board scope2count=1 scope2_0_kind=Board scope2_0_value=Board commentlength=78 connectstyle=Direct reliefconductorwidth=10 reliefentries=4 polygonreliefangle="90 Angle" // Protel DXP Scope 2 Expression Was: IsNamedPolygon('POWER_LAYER_OUTB_P050')
PolygonConnect PolygonConnect_29 [All] p0 off: scope1count=1 scope1_0_kind=Board scope1_0_value=Board scope2count=1 scope2_0_kind=Board scope2_0_value=Board commentlength=78 connectstyle=Direct reliefconductorwidth=10 reliefentries=4 polygonreliefangle="90 Angle" // Protel DXP Scope 2 Expression Was: IsNamedPolygon('POWER_LAYER_OUTC_P048')
PolygonConnect PolygonConnect_28 [All] p0 off: scope1count=1 scope1_0_kind=Board scope1_0_value=Board scope2count=1 scope2_0_kind=Board scope2_0_value=Board commentlength=78 connectstyle=Direct reliefconductorwidth=10 reliefentries=4 polygonreliefangle="90 Angle" // Protel DXP Scope 2 Expression Was: IsNamedPolygon('POWER_LAYER_AVDD_P064')
PolygonConnect PolygonConnect_27 [All] p0 off: scope1count=1 scope1_0_kind=Board scope1_0_value=Board scope2count=1 scope2_0_kind=Board scope2_0_value=Board commentlength=81 connectstyle=Direct reliefconductorwidth=10 reliefentries=4 polygonreliefangle="90 Angle" // Protel DXP Scope 2 Expression Was: IsNamedPolygon('SIGNAL_LAYER_1_OUTA_P060')
PolygonConnect PolygonConnect_26 [All] p0 off: scope1count=1 scope1_0_kind=Board scope1_0_value=Board scope2count=1 scope2_0_kind=Board scope2_0_value=Board commentlength=81 connectstyle=Direct reliefconductorwidth=10 reliefentries=4 polygonreliefangle="90 Angle" // Protel DXP Scope 2 Expression Was: IsNamedPolygon('SIGNAL_LAYER_1_OUTB_P058')
PolygonConnect PolygonConnect_25 [All] p0 off: scope1count=1 scope1_0_kind=Board scope1_0_value=Board scope2count=1 scope2_0_kind=Board scope2_0_value=Board commentlength=81 connectstyle=Direct reliefconductorwidth=10 reliefentries=4 polygonreliefangle="90 Angle" // Protel DXP Scope 2 Expression Was: IsNamedPolygon('SIGNAL_LAYER_1_OUTC_P056')
PolygonConnect PolygonConnect_24 [All] p0 off: scope1count=1 scope1_0_kind=Board scope1_0_value=Board scope2count=1 scope2_0_kind=Board scope2_0_value=Board commentlength=81 connectstyle=Direct reliefconductorwidth=10 reliefentries=4 polygonreliefangle="90 Angle" // Protel DXP Scope 2 Expression Was: IsNamedPolygon('SIGNAL_LAYER_2_PVDD_P054')
PolygonConnect PolygonConnect_23 [All] p0 off: scope1count=1 scope1_0_kind=Board scope1_0_value=Board scope2count=1 scope2_0_kind=Board scope2_0_value=Board commentlength=81 connectstyle=Direct reliefconductorwidth=10 reliefentries=4 polygonreliefangle="90 Angle" // Protel DXP Scope 2 Expression Was: IsNamedPolygon('SIGNAL_LAYER_2_PVDD_P052')
PolygonConnect PolygonConnect_22 [All] p0 off: scope1count=1 scope1_0_kind=Board scope1_0_value=Board scope2count=1 scope2_0_kind=Board scope2_0_value=Board commentlength=81 connectstyle=Direct reliefconductorwidth=10 reliefentries=4 polygonreliefangle="90 Angle" // Protel DXP Scope 2 Expression Was: IsNamedPolygon('SIGNAL_LAYER_2_OUTA_P050')
PolygonConnect PolygonConnect_21 [All] p0 off: scope1count=1 scope1_0_kind=Board scope1_0_value=Board scope2count=1 scope2_0_kind=Board scope2_0_value=Board commentlength=81 connectstyle=Direct reliefconductorwidth=10 reliefentries=4 polygonreliefangle="90 Angle" // Protel DXP Scope 2 Expression Was: IsNamedPolygon('SIGNAL_LAYER_2_OUTB_P048')
PolygonConnect PolygonConnect_20 [All] p0 off: scope1count=1 scope1_0_kind=Board scope1_0_value=Board scope2count=1 scope2_0_kind=Board scope2_0_value=Board commentlength=81 connectstyle=Direct reliefconductorwidth=10 reliefentries=4 polygonreliefangle="90 Angle" // Protel DXP Scope 2 Expression Was: IsNamedPolygon('SIGNAL_LAYER_2_OUTC_P046')
PolygonConnect PolygonConnect_19 [All] p0 off: scope1count=1 scope1_0_kind=Board scope1_0_value=Board scope2count=1 scope2_0_kind=Board scope2_0_value=Board commentlength=76 connectstyle=Direct reliefconductorwidth=10 reliefentries=4 polygonreliefangle="90 Angle" // Protel DXP Scope 2 Expression Was: IsNamedPolygon('TOP_LAYER_AVDD_P046')
PolygonConnect PolygonConnect_18 [All] p0 off: scope1count=1 scope1_0_kind=Board scope1_0_value=Board scope2count=1 scope2_0_kind=Board scope2_0_value=Board commentlength=76 connectstyle=Direct reliefconductorwidth=10 reliefentries=4 polygonreliefangle="90 Angle" // Protel DXP Scope 2 Expression Was: IsNamedPolygon('TOP_LAYER_PVDD_P034')
PolygonConnect PolygonConnect_17 [All] p0 off: scope1count=1 scope1_0_kind=Board scope1_0_value=Board scope2count=1 scope2_0_kind=Board scope2_0_value=Board commentlength=81 connectstyle=Direct reliefconductorwidth=10 reliefentries=4 polygonreliefangle="90 Angle" // Protel DXP Scope 2 Expression Was: IsNamedPolygon('SIGNAL_LAYER_1_OUTC_P036')
PolygonConnect PolygonConnect_16 [All] p0 off: scope1count=1 scope1_0_kind=Board scope1_0_value=Board scope2count=1 scope2_0_kind=Board scope2_0_value=Board commentlength=76 connectstyle=Direct reliefconductorwidth=10 reliefentries=4 polygonreliefangle="90 Angle" // Protel DXP Scope 2 Expression Was: IsNamedPolygon('TOP_LAYER_PVDD_P034')
PolygonConnect PolygonConnect_15 [All] p0 off: scope1count=1 scope1_0_kind=Board scope1_0_value=Board scope2count=1 scope2_0_kind=Board scope2_0_value=Board commentlength=75 connectstyle=Direct reliefconductorwidth=10 reliefentries=4 polygonreliefangle="90 Angle" // Protel DXP Scope 2 Expression Was: IsNamedPolygon('TOP_LAYER_LSS_P030')
PolygonConnect PolygonConnect_14 [All] p0 off: scope1count=1 scope1_0_kind=Board scope1_0_value=Board scope2count=1 scope2_0_kind=Board scope2_0_value=Board commentlength=79 connectstyle=Direct reliefconductorwidth=10 reliefentries=4 polygonreliefangle="90 Angle" // Protel DXP Scope 2 Expression Was: IsNamedPolygon('TOP_LAYER_GLC_FET_P024')
PolygonConnect PolygonConnect_13 [All] p0 off: scope1count=1 scope1_0_kind=Board scope1_0_value=Board scope2count=1 scope2_0_kind=Board scope2_0_value=Board commentlength=79 connectstyle=Direct reliefconductorwidth=10 reliefentries=4 polygonreliefangle="90 Angle" // Protel DXP Scope 2 Expression Was: IsNamedPolygon('TOP_LAYER_GLB_FET_P026')
PolygonConnect PolygonConnect_12 [All] p0 off: scope1count=1 scope1_0_kind=Board scope1_0_value=Board scope2count=1 scope2_0_kind=Board scope2_0_value=Board commentlength=79 connectstyle=Direct reliefconductorwidth=10 reliefentries=4 polygonreliefangle="90 Angle" // Protel DXP Scope 2 Expression Was: IsNamedPolygon('TOP_LAYER_GLA_FET_P028')
PolygonConnect PolygonConnect_11 [All] p0 off: scope1count=1 scope1_0_kind=Board scope1_0_value=Board scope2count=1 scope2_0_kind=Board scope2_0_value=Board commentlength=79 connectstyle=Direct reliefconductorwidth=10 reliefentries=4 polygonreliefangle="90 Angle" // Protel DXP Scope 2 Expression Was: IsNamedPolygon('TOP_LAYER_GHB_FET_P020')
PolygonConnect PolygonConnect_10 [All] p0 off: scope1count=1 scope1_0_kind=Board scope1_0_value=Board scope2count=1 scope2_0_kind=Board scope2_0_value=Board commentlength=79 connectstyle=Direct reliefconductorwidth=10 reliefentries=4 polygonreliefangle="90 Angle" // Protel DXP Scope 2 Expression Was: IsNamedPolygon('TOP_LAYER_GHA_FET_P022')
PolygonConnect PolygonConnect_9 [All] p0 off: scope1count=1 scope1_0_kind=Board scope1_0_value=Board scope2count=1 scope2_0_kind=Board scope2_0_value=Board commentlength=79 connectstyle=Direct reliefconductorwidth=10 reliefentries=4 polygonreliefangle="90 Angle" // Protel DXP Scope 2 Expression Was: IsNamedPolygon('TOP_LAYER_GHC_FET_P018')
PolygonConnect PolygonConnect_8 [All] p0 off: scope1count=1 scope1_0_kind=Board scope1_0_value=Board scope2count=1 scope2_0_kind=Board scope2_0_value=Board commentlength=75 connectstyle=Direct reliefconductorwidth=10 reliefentries=4 polygonreliefangle="90 Angle" // Protel DXP Scope 2 Expression Was: IsNamedPolygon('TOP_LAYER_GND_P014')
PolygonConnect PolygonConnect_7 [All] p0 off: scope1count=1 scope1_0_kind=Board scope1_0_value=Board scope2count=1 scope2_0_kind=Board scope2_0_value=Board commentlength=75 connectstyle=Direct reliefconductorwidth=10 reliefentries=4 polygonreliefangle="90 Angle" // Protel DXP Scope 2 Expression Was: IsNamedPolygon('TOP_LAYER_GND_P014')
PolygonConnect PolygonConnect_6 [All] p0 off: scope1count=1 scope1_0_kind=Board scope1_0_value=Board scope2count=1 scope2_0_kind=Board scope2_0_value=Board commentlength=76 connectstyle=Direct reliefconductorwidth=10 reliefentries=4 polygonreliefangle="90 Angle" // Protel DXP Scope 2 Expression Was: IsNamedPolygon('TOP_LAYER_PVDD_P008')
PolygonConnect PolygonConnect_5 [All] p0 off: scope1count=1 scope1_0_kind=Board scope1_0_value=Board scope2count=1 scope2_0_kind=Board scope2_0_value=Board commentlength=76 connectstyle=Direct reliefconductorwidth=10 reliefentries=4 polygonreliefangle="90 Angle" // Protel DXP Scope 2 Expression Was: IsNamedPolygon('TOP_LAYER_PVDD_P008')
PolygonConnect PolygonConnect_4 [All] p0 off: scope1count=1 scope1_0_kind=Board scope1_0_value=Board scope2count=1 scope2_0_kind=Board scope2_0_value=Board commentlength=76 connectstyle=Direct reliefconductorwidth=10 reliefentries=4 polygonreliefangle="90 Angle" // Protel DXP Scope 2 Expression Was: IsNamedPolygon('TOP_LAYER_PVDD_P008')
PolygonConnect PolygonConnect_3 [All] p0 off: scope1count=1 scope1_0_kind=Board scope1_0_value=Board scope2count=1 scope2_0_kind=Board scope2_0_value=Board commentlength=76 connectstyle=Direct reliefconductorwidth=10 reliefentries=4 polygonreliefangle="90 Angle" // Protel DXP Scope 2 Expression Was: IsNamedPolygon('TOP_LAYER_OUTA_P006')
PolygonConnect PolygonConnect_2 [All] p0 off: scope1count=1 scope1_0_kind=Board scope1_0_value=Board scope2count=1 scope2_0_kind=Board scope2_0_value=Board commentlength=76 connectstyle=Direct reliefconductorwidth=10 reliefentries=4 polygonreliefangle="90 Angle" // Protel DXP Scope 2 Expression Was: IsNamedPolygon('TOP_LAYER_OUTB_P004')
PolygonConnect PolygonConnect_1 [All] p0 off: scope1count=1 scope1_0_kind=Board scope1_0_value=Board scope2count=1 scope2_0_kind=Board scope2_0_value=Board commentlength=76 connectstyle=Direct reliefconductorwidth=10 reliefentries=4 polygonreliefangle="90 Angle" // Protel DXP Scope 2 Expression Was: IsNamedPolygon('TOP_LAYER_OUTC_P002')
PolygonConnect [All] p0: scope1count=1 scope1_0_kind=Board scope1_0_value=Board scope2count=1 scope2_0_kind=Board scope2_0_value=Board commentlength=0 connectstyle=Relief reliefconductorwidth=10 reliefentries=4 polygonreliefangle="90 Angle"
PolygonConnect PolygonConnect_51 [All] p1: connectstyle=Direct reliefconductorwidth=10 reliefentries=4 polygonreliefangle="90 Angle" airgapwidth=10
PolygonConnect PolygonConnect_50 [All vs IsNamedPolygon('TOP_LAYER_PVDD_P078')] p2: connectstyle=Direct reliefconductorwidth=10 reliefentries=4 polygonreliefangle="90 Angle" airgapwidth=10
PolygonConnect PolygonConnect_49 [All vs IsNamedPolygon('TOP_LAYER_PVDD_P078')] p3: connectstyle=Direct reliefconductorwidth=10 reliefentries=4 polygonreliefangle="90 Angle" airgapwidth=10
PolygonConnect PolygonConnect_48 [All vs IsNamedPolygon('TOP_LAYER_PVDD_P078')] p4: connectstyle=Direct reliefconductorwidth=10 reliefentries=4 polygonreliefangle="90 Angle" airgapwidth=10
PolygonConnect PolygonConnect_47 [All vs IsNamedPolygon('TOP_LAYER_PVDD_P008')] p5: thpad.connectstyle=Direct thpad.reliefconductorwidth=10 thpad.reliefentries=4 thpad.polygonreliefangle="90 Angle" thpad.airgapwidth=10 smdpad.connectstyle=Direct smdpad.reliefconductorwidth=10 smdpad.reliefentries=4 smdpad.polygonreliefangle="90 Angle" smdpad.airgapwidth=10 via.connectstyle=Relief via.reliefconductorwidth=10 via.reliefentries=4 via.polygonreliefangle="90 Angle" via.airgapwidth=10
PolygonConnect PolygonConnect_46 [All vs IsNamedPolygon('BOTTOM_LAYER_GND_P080')] p6: connectstyle=Direct reliefconductorwidth=10 reliefentries=4 polygonreliefangle="90 Angle" airgapwidth=10
PolygonConnect PolygonConnect_45 [All vs IsNamedPolygon('BOTTOM_LAYER_OUTA_P076')] p7: connectstyle=Direct reliefconductorwidth=10 reliefentries=4 polygonreliefangle="90 Angle" airgapwidth=10
PolygonConnect PolygonConnect_44 [All vs IsNamedPolygon('BOTTOM_LAYER_OUTB_P074')] p8: connectstyle=Direct reliefconductorwidth=10 reliefentries=4 polygonreliefangle="90 Angle" airgapwidth=10
PolygonConnect PolygonConnect_43 [All vs IsNamedPolygon('BOTTOM_LAYER_OUTC_P072')] p9: connectstyle=Direct reliefconductorwidth=10 reliefentries=4 polygonreliefangle="90 Angle" airgapwidth=10
PolygonConnect PolygonConnect_42 [All vs IsNamedPolygon('BOTTOM_LAYER_NONET_P070')] p10: connectstyle=Direct reliefconductorwidth=10 reliefentries=4 polygonreliefangle="90 Angle" airgapwidth=10
PolygonConnect PolygonConnect_41 [All vs IsNamedPolygon('POWER_LAYER_GND_P078')] p11: connectstyle=Direct reliefconductorwidth=10 reliefentries=4 polygonreliefangle="90 Angle" airgapwidth=10
PolygonConnect PolygonConnect_40 [All vs IsNamedPolygon('GND_LAYER_GND_P074')] p12: connectstyle=Direct reliefconductorwidth=10 reliefentries=4 polygonreliefangle="90 Angle" airgapwidth=10
PolygonConnect PolygonConnect_39 [All vs IsNamedPolygon('TOP_LAYER_GND_P070')] p13: connectstyle=Direct reliefconductorwidth=10 reliefentries=4 polygonreliefangle="90 Angle" airgapwidth=10
PolygonConnect PolygonConnect_38 [All vs IsNamedPolygon('BOTTOM_LAYER_GND')] p14: connectstyle=Direct reliefconductorwidth=10 reliefentries=4 polygonreliefangle="90 Angle" airgapwidth=10
PolygonConnect PolygonConnect_37 [All vs IsNamedPolygon('BOTTOM_LAYER_GND')] p15: connectstyle=Direct reliefconductorwidth=10 reliefentries=4 polygonreliefangle="90 Angle" airgapwidth=10
PolygonConnect PolygonConnect_36 [All vs IsNamedPolygon('GND_LAYER_OUTA_P062')] p16: connectstyle=Direct reliefconductorwidth=10 reliefentries=4 polygonreliefangle="90 Angle" airgapwidth=10
PolygonConnect PolygonConnect_35 [All vs IsNamedPolygon('GND_LAYER_OUTB_P060')] p17: connectstyle=Direct reliefconductorwidth=10 reliefentries=4 polygonreliefangle="90 Angle" airgapwidth=10
PolygonConnect PolygonConnect_34 [All vs IsNamedPolygon('GND_LAYER_OUTC_P058')] p18: connectstyle=Direct reliefconductorwidth=10 reliefentries=4 polygonreliefangle="90 Angle" airgapwidth=10
PolygonConnect PolygonConnect_33 [All vs IsNamedPolygon('POWER_LAYER_PVDD_P056')] p19: connectstyle=Direct reliefconductorwidth=10 reliefentries=4 polygonreliefangle="90 Angle" airgapwidth=10
PolygonConnect PolygonConnect_32 [All vs IsNamedPolygon('POWER_LAYER_PVDD_P056')] p20: connectstyle=Direct reliefconductorwidth=10 reliefentries=4 polygonreliefangle="90 Angle" airgapwidth=10
PolygonConnect PolygonConnect_31 [All vs IsNamedPolygon('POWER_LAYER_OUTA_P052')] p21: connectstyle=Direct reliefconductorwidth=10 reliefentries=4 polygonreliefangle="90 Angle" airgapwidth=10
PolygonConnect PolygonConnect_30 [All vs IsNamedPolygon('POWER_LAYER_OUTB_P050')] p22: connectstyle=Direct reliefconductorwidth=10 reliefentries=4 polygonreliefangle="90 Angle" airgapwidth=10
PolygonConnect PolygonConnect_29 [All vs IsNamedPolygon('POWER_LAYER_OUTC_P048')] p23: connectstyle=Direct reliefconductorwidth=10 reliefentries=4 polygonreliefangle="90 Angle" airgapwidth=10
PolygonConnect PolygonConnect_28 [All vs IsNamedPolygon('POWER_LAYER_AVDD_P064')] p24: connectstyle=Direct reliefconductorwidth=10 reliefentries=4 polygonreliefangle="90 Angle" airgapwidth=10
PolygonConnect PolygonConnect_27 [All vs IsNamedPolygon('SIGNAL_LAYER_1_OUTA_P060')] p25: connectstyle=Direct reliefconductorwidth=10 reliefentries=4 polygonreliefangle="90 Angle" airgapwidth=10
PolygonConnect PolygonConnect_26 [All vs IsNamedPolygon('SIGNAL_LAYER_1_OUTB_P058')] p26: connectstyle=Direct reliefconductorwidth=10 reliefentries=4 polygonreliefangle="90 Angle" airgapwidth=10
PolygonConnect PolygonConnect_25 [All vs IsNamedPolygon('SIGNAL_LAYER_1_OUTC_P056')] p27: connectstyle=Direct reliefconductorwidth=10 reliefentries=4 polygonreliefangle="90 Angle" airgapwidth=10
PolygonConnect PolygonConnect_24 [All vs IsNamedPolygon('SIGNAL_LAYER_2_PVDD_P054')] p28: connectstyle=Direct reliefconductorwidth=10 reliefentries=4 polygonreliefangle="90 Angle" airgapwidth=10
PolygonConnect PolygonConnect_23 [All vs IsNamedPolygon('SIGNAL_LAYER_2_PVDD_P052')] p29: connectstyle=Direct reliefconductorwidth=10 reliefentries=4 polygonreliefangle="90 Angle" airgapwidth=10
PolygonConnect PolygonConnect_22 [All vs IsNamedPolygon('SIGNAL_LAYER_2_OUTA_P050')] p30: connectstyle=Direct reliefconductorwidth=10 reliefentries=4 polygonreliefangle="90 Angle" airgapwidth=10
PolygonConnect PolygonConnect_21 [All vs IsNamedPolygon('SIGNAL_LAYER_2_OUTB_P048')] p31: connectstyle=Direct reliefconductorwidth=10 reliefentries=4 polygonreliefangle="90 Angle" airgapwidth=10
PolygonConnect PolygonConnect_20 [All vs IsNamedPolygon('SIGNAL_LAYER_2_OUTC_P046')] p32: connectstyle=Direct reliefconductorwidth=10 reliefentries=4 polygonreliefangle="90 Angle" airgapwidth=10
PolygonConnect PolygonConnect_19 [All vs IsNamedPolygon('TOP_LAYER_AVDD_P046')] p33: connectstyle=Direct reliefconductorwidth=10 reliefentries=4 polygonreliefangle="90 Angle" airgapwidth=10
PolygonConnect PolygonConnect_18 [All vs IsNamedPolygon('TOP_LAYER_PVDD_P034')] p34: connectstyle=Direct reliefconductorwidth=10 reliefentries=4 polygonreliefangle="90 Angle" airgapwidth=10
PolygonConnect PolygonConnect_17 [All vs IsNamedPolygon('SIGNAL_LAYER_1_OUTC_P036')] p35: connectstyle=Direct reliefconductorwidth=10 reliefentries=4 polygonreliefangle="90 Angle" airgapwidth=10
PolygonConnect PolygonConnect_16 [All vs IsNamedPolygon('TOP_LAYER_PVDD_P034')] p36: connectstyle=Direct reliefconductorwidth=10 reliefentries=4 polygonreliefangle="90 Angle" airgapwidth=10
PolygonConnect PolygonConnect_15 [All vs IsNamedPolygon('TOP_LAYER_LSS_P030')] p37: connectstyle=Direct reliefconductorwidth=10 reliefentries=4 polygonreliefangle="90 Angle" airgapwidth=10
PolygonConnect PolygonConnect_14 [All vs IsNamedPolygon('TOP_LAYER_GLC_FET_P024')] p38: connectstyle=Direct reliefconductorwidth=10 reliefentries=4 polygonreliefangle="90 Angle" airgapwidth=10
PolygonConnect PolygonConnect_13 [All vs IsNamedPolygon('TOP_LAYER_GLB_FET_P026')] p39: connectstyle=Direct reliefconductorwidth=10 reliefentries=4 polygonreliefangle="90 Angle" airgapwidth=10
PolygonConnect PolygonConnect_12 [All vs IsNamedPolygon('TOP_LAYER_GLA_FET_P028')] p40: connectstyle=Direct reliefconductorwidth=10 reliefentries=4 polygonreliefangle="90 Angle" airgapwidth=10
PolygonConnect PolygonConnect_11 [All vs IsNamedPolygon('TOP_LAYER_GHB_FET_P020')] p41: connectstyle=Direct reliefconductorwidth=10 reliefentries=4 polygonreliefangle="90 Angle" airgapwidth=10
PolygonConnect PolygonConnect_10 [All vs IsNamedPolygon('TOP_LAYER_GHA_FET_P022')] p42: connectstyle=Direct reliefconductorwidth=10 reliefentries=4 polygonreliefangle="90 Angle" airgapwidth=10
PolygonConnect PolygonConnect_9 [All vs IsNamedPolygon('TOP_LAYER_GHC_FET_P018')] p43: connectstyle=Direct reliefconductorwidth=10 reliefentries=4 polygonreliefangle="90 Angle" airgapwidth=10
PolygonConnect PolygonConnect_8 [All vs IsNamedPolygon('TOP_LAYER_GND_P014')] p44: connectstyle=Direct reliefconductorwidth=10 reliefentries=4 polygonreliefangle="90 Angle" airgapwidth=10
PolygonConnect PolygonConnect_7 [All vs IsNamedPolygon('TOP_LAYER_GND_P014')] p45: connectstyle=Direct reliefconductorwidth=10 reliefentries=4 polygonreliefangle="90 Angle" airgapwidth=10
PolygonConnect PolygonConnect_6 [All vs IsNamedPolygon('TOP_LAYER_PVDD_P008')] p46: connectstyle=Direct reliefconductorwidth=10 reliefentries=4 polygonreliefangle="90 Angle" airgapwidth=10
PolygonConnect PolygonConnect_5 [All vs IsNamedPolygon('TOP_LAYER_PVDD_P008')] p47: connectstyle=Direct reliefconductorwidth=10 reliefentries=4 polygonreliefangle="90 Angle" airgapwidth=10
PolygonConnect PolygonConnect_4 [All vs IsNamedPolygon('TOP_LAYER_PVDD_P008')] p48: connectstyle=Direct reliefconductorwidth=10 reliefentries=4 polygonreliefangle="90 Angle" airgapwidth=10
PolygonConnect PolygonConnect_3 [All vs IsNamedPolygon('TOP_LAYER_OUTA_P006')] p49: connectstyle=Direct reliefconductorwidth=10 reliefentries=4 polygonreliefangle="90 Angle" airgapwidth=10
PolygonConnect PolygonConnect_2 [All vs IsNamedPolygon('TOP_LAYER_OUTB_P004')] p50: connectstyle=Direct reliefconductorwidth=10 reliefentries=4 polygonreliefangle="90 Angle" airgapwidth=10
PolygonConnect PolygonConnect_1 [All vs IsNamedPolygon('TOP_LAYER_OUTC_P002')] p51: connectstyle=Direct reliefconductorwidth=10 reliefentries=4 polygonreliefangle="90 Angle" airgapwidth=10
PolygonConnect [All] p52: connectstyle=Relief reliefconductorwidth=10 reliefentries=4 polygonreliefangle="90 Angle" airgapwidth=10
RoutingCorners [All] p0: scope1count=1 scope1_0_kind=Board scope1_0_value=Board scope2count=1 scope2_0_kind=Board scope2_0_value=Board commentlength=0 cornerstyle=45-Degree minsetback=100 maxsetback=100
RoutingLayers [All] p0: scope1count=1 scope1_0_kind=Board scope1_0_value=Board scope2count=1 scope2_0_kind=Board scope2_0_value=Board commentlength=0 top layer=Automatic mid layer 1=Automatic mid layer 2=Automatic bottom layer=Automatic
RoutingPriority [All] p0: scope1count=1 scope1_0_kind=Board scope1_0_value=Board scope2count=1 scope2_0_kind=Board scope2_0_value=Board commentlength=0
RoutingTopology [All] p0: scope1count=1 scope1_0_kind=Board scope1_0_value=Board scope2count=1 scope2_0_kind=Board scope2_0_value=Board commentlength=0 topology=Shortest
RoutingVias [All] p0: scope1count=1 scope1_0_kind=Board scope1_0_value=Board scope2count=1 scope2_0_kind=Board scope2_0_value=Board commentlength=0 holewidth=7.87 width=19.68 viastyle="Through Hole" minholewidth=7.87 minwidth=19.68 maxholewidth=10 maxwidth=20
RoutingVias ThermalPadVias [All] p0 off: scope1count=1 scope1_0_kind=Board scope1_0_value=Board scope2count=1 scope2_0_kind=Board scope2_0_value=Board commentlength=63 holewidth=7.87 width=19.68 viastyle="Through Hole" minholewidth=7.87 minwidth=19.68 maxholewidth=12.99 maxwidth=23.62 // Protel DXP Scope 1 Expression Was: IsVia and InAnyComponent
RoutingVias ThermalPadVias [IsVia and InAnyComponent] p1: holewidth=7.87 width=19.68 viastyle="Through Hole" minholewidth=7.87 minwidth=19.68 maxholewidth=12.99 maxwidth=23.62
RoutingVias [All] p2: holewidth=7.87 width=19.68 viastyle="Through Hole" minholewidth=7.87 minwidth=19.68 maxholewidth=10 maxwidth=20
ShortCircuit [All] p0: scope1count=1 scope1_0_kind=Board scope1_0_value=Board scope2count=1 scope2_0_kind=Board scope2_0_value=Board commentlength=0 allowed=FALSE
SilkToBoardRegionClearance [All] p0 off: scope1count=1 scope1_0_kind=Board scope1_0_value=Board scope2count=1 scope2_0_kind=Board scope2_0_value=Board commentlength=130 // Protel DXP Scope 1 Expression Was: Not ((IsComment or IsDesignator) And (Hide <> 'False')) and not InRegion(1000,500,4000,800)
SilkToBoardRegionClearance [Not ((IsComment or IsDesignator) And (Hide <> 'False')) and not InRegion(1000,500,4000,800)] p1:
SilkToSilkClearance [All] p0: scope1count=1 scope1_0_kind=Board scope1_0_value=Board scope2count=1 scope2_0_kind=Board scope2_0_value=Board commentlength=0
SilkToSilkClearance SilkToSilkClearance_Pb-FreeLogo [All] p0 off: scope1count=1 scope1_0_kind=Board scope1_0_value=Board scope2count=1 scope2_0_kind=Board scope2_0_value=Board commentlength=120 // Protel DXP Scope 2 Expression Was: (HasFootprint('Pb-Free_Overlay_Medium') OR HasFootprint('Pb-Free_Overlay_Small'))
SilkToSilkClearance SilkToSilkClearance_Pb-FreeLogo [(HasFootprint('Pb-Free_Overlay_Medium') OR HasFootprint('Pb-Free_Overlay_Small')) vs (HasFootprint('Pb-Free_Overlay_Medium') OR HasFootprint('Pb-Free_Overlay_Small'))] p1: silktosilkclearance=0
SilkToSilkClearance [All] p2: silktosilkclearance=0
SilkToSolderMaskClearance "Silk to Solder Mask Opening" [All] p0: scope1count=1 scope1_0_kind=Board scope1_0_value=Board scope2count=1 scope2_0_kind=Board scope2_0_value=Board commentlength=0
SilkToSolderMaskClearance SilkToComponentPadClearance [All] p0 off: scope1count=1 scope1_0_kind=Board scope1_0_value=Board scope2count=1 scope2_0_kind=Board scope2_0_value=Board commentlength=87 // Protel DXP Scope 1 Expression Was: (IsPad or IsFill or IsRegion) and InAnycomponent
SilkToSolderMaskClearance SilkToComponentPadClearance [(IsPad or IsFill or IsRegion) and InAnycomponent] p1: minsilkscreentomaskgap=0 clearancetoexposedcopper=TRUE
SilkToSolderMaskClearance "Silk to Solder Mask Opening" [All] p2: minsilkscreentomaskgap=0 clearancetoexposedcopper=FALSE
SolderMaskExpansion [All] p0: scope1count=1 scope1_0_kind=Board scope1_0_value=Board scope2count=1 scope2_0_kind=Board scope2_0_value=Board commentlength=0 expansion=1.97
SolderMaskExpansion [All] p1: expansion=1.97
UnRoutedNet [All] p0: scope1count=1 scope1_0_kind=Board scope1_0_value=Board scope2count=1 scope2_0_kind=Board scope2_0_value=Board commentlength=0
UnRoutedNet [All] p1: checkbadconnections=TRUE
UnpouredPolygon [All] p0: scope1count=1 scope1_0_kind=Board scope1_0_value=Board scope2count=1 scope2_0_kind=Board scope2_0_value=Board commentlength=0
Width [All] p0: scope1count=1 scope1_0_kind=Board scope1_0_value=Board scope2count=1 scope2_0_kind=Board scope2_0_value=Board commentlength=0 maxlimit=100 minlimit=6 preferedwidth=10
Width [All] p1: maxlimit=100 minlimit=6 preferedwidth=10 checkconnectedcopper=TRUE
13 further rules are at their usual default settings.

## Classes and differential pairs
component class MD053A_LDO: C2 C33 C34 C35 C37 J8 J16 SH-J5 SH-J9 U3
component class Label: LBL1
component class Shunt: SH-J1 SH-J2 SH-J3 SH-J4 SH-J5 SH-J6 SH-J7 SH-J8 SH-J9
component class MD053A_POWER_AND_CONNECTORS: C36 C38 C39 C40 C41 C42 C43 C44 C45 C46 C47 C48 D11 D12 GND1 GND2 GND3 J9 J10 J11 J12 J13 J14 J15 R37 R62 R63 R64 R65 R66 R67 R68 R69 R70 R71 R72 R73 R74 R75 R76 R77 R78 R80 R81 R82 R83 R84 R85 R86 R87 R88 R89 R90 R91 R92 S1 S2 SH-J6 SH-J7 SH-J8 TP21 TP22 TP23 TP24 TP25 TP26 TP27 TP28 TP29 TP30 TP31 TP34 TP35 TP36 TP37 TP38 U4
component class MD053A_FETS_AND_POWER_STAGE: C10 C11 C12 C13 C14 C15 C16 C17 C18 C19 C20 C21 C22 C23 C24 C25 C26 C27 C28 C29 C30 C31 C32 D5 D6 D7 D8 D9 D10 NT1 NT2 NT3 Q1 Q2 Q3 Q4 Q5 Q6 R40 R41 R42 R43 R44 R45 R46 R47 R48 R49 R50 R51 R52 R53 R54 R55 R56 R57 R58 R59 R60 R61 TP15 TP16 TP17 TP18 TP19 TP20 TP32 TP33 U2
component class MD053A_DRIVER: C1 C3 C4 C5 C6 C7 C8 C9 C49 D1 D2 D3 D4 J1 J2 J3 J4 J5 J6 J7 R1 R2 R3 R4 R5 R6 R7 R8 R9 R10 R11 R12 R13 R14 R15 R16 R17 R18 R19 R20 R21 R22 R23 R24 R25 R26 R27 R28 R29 R30 R31 R32 R33 R34 R35 R36 R38 R39 SH-J1 SH-J2 SH-J3 SH-J4 TP1 TP2 TP3 TP4 TP5 TP6 TP7 TP8 TP9 TP10 TP11 TP12 TP13 TP14 U1
component class Header: J1 J2 J3 J4 J5 J8 J11 J13 J14 J15 J16
component class "Mounting Holes": H1 H2 H3 H4
component class Logo: Logo2
component class MD053A_Hardware: FID1 FID2 FID3 H1 H2 H3 H4 H5 H6 H7 H8 LBL1 Logo1 Logo2 Logo3 Logo4 LOGO5 LOGO6 LOGO7 ZZ1 ZZ2 ZZ3 ZZ4
component class FiducialMark: FID1 FID2 FID3
component class AssemblyNote: ZZ1 ZZ2 ZZ3 ZZ4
